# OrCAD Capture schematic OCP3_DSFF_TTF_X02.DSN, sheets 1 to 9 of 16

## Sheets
1 PAGE01 - Block Diagram: size Custom; title: OCP NIC 3.0 DSFF Thermal Test Fixture; rev: X02; company: Dell, Inc.; note: 9XNGK; note: 200 Dell Way; note: Round Rock, TX 78682
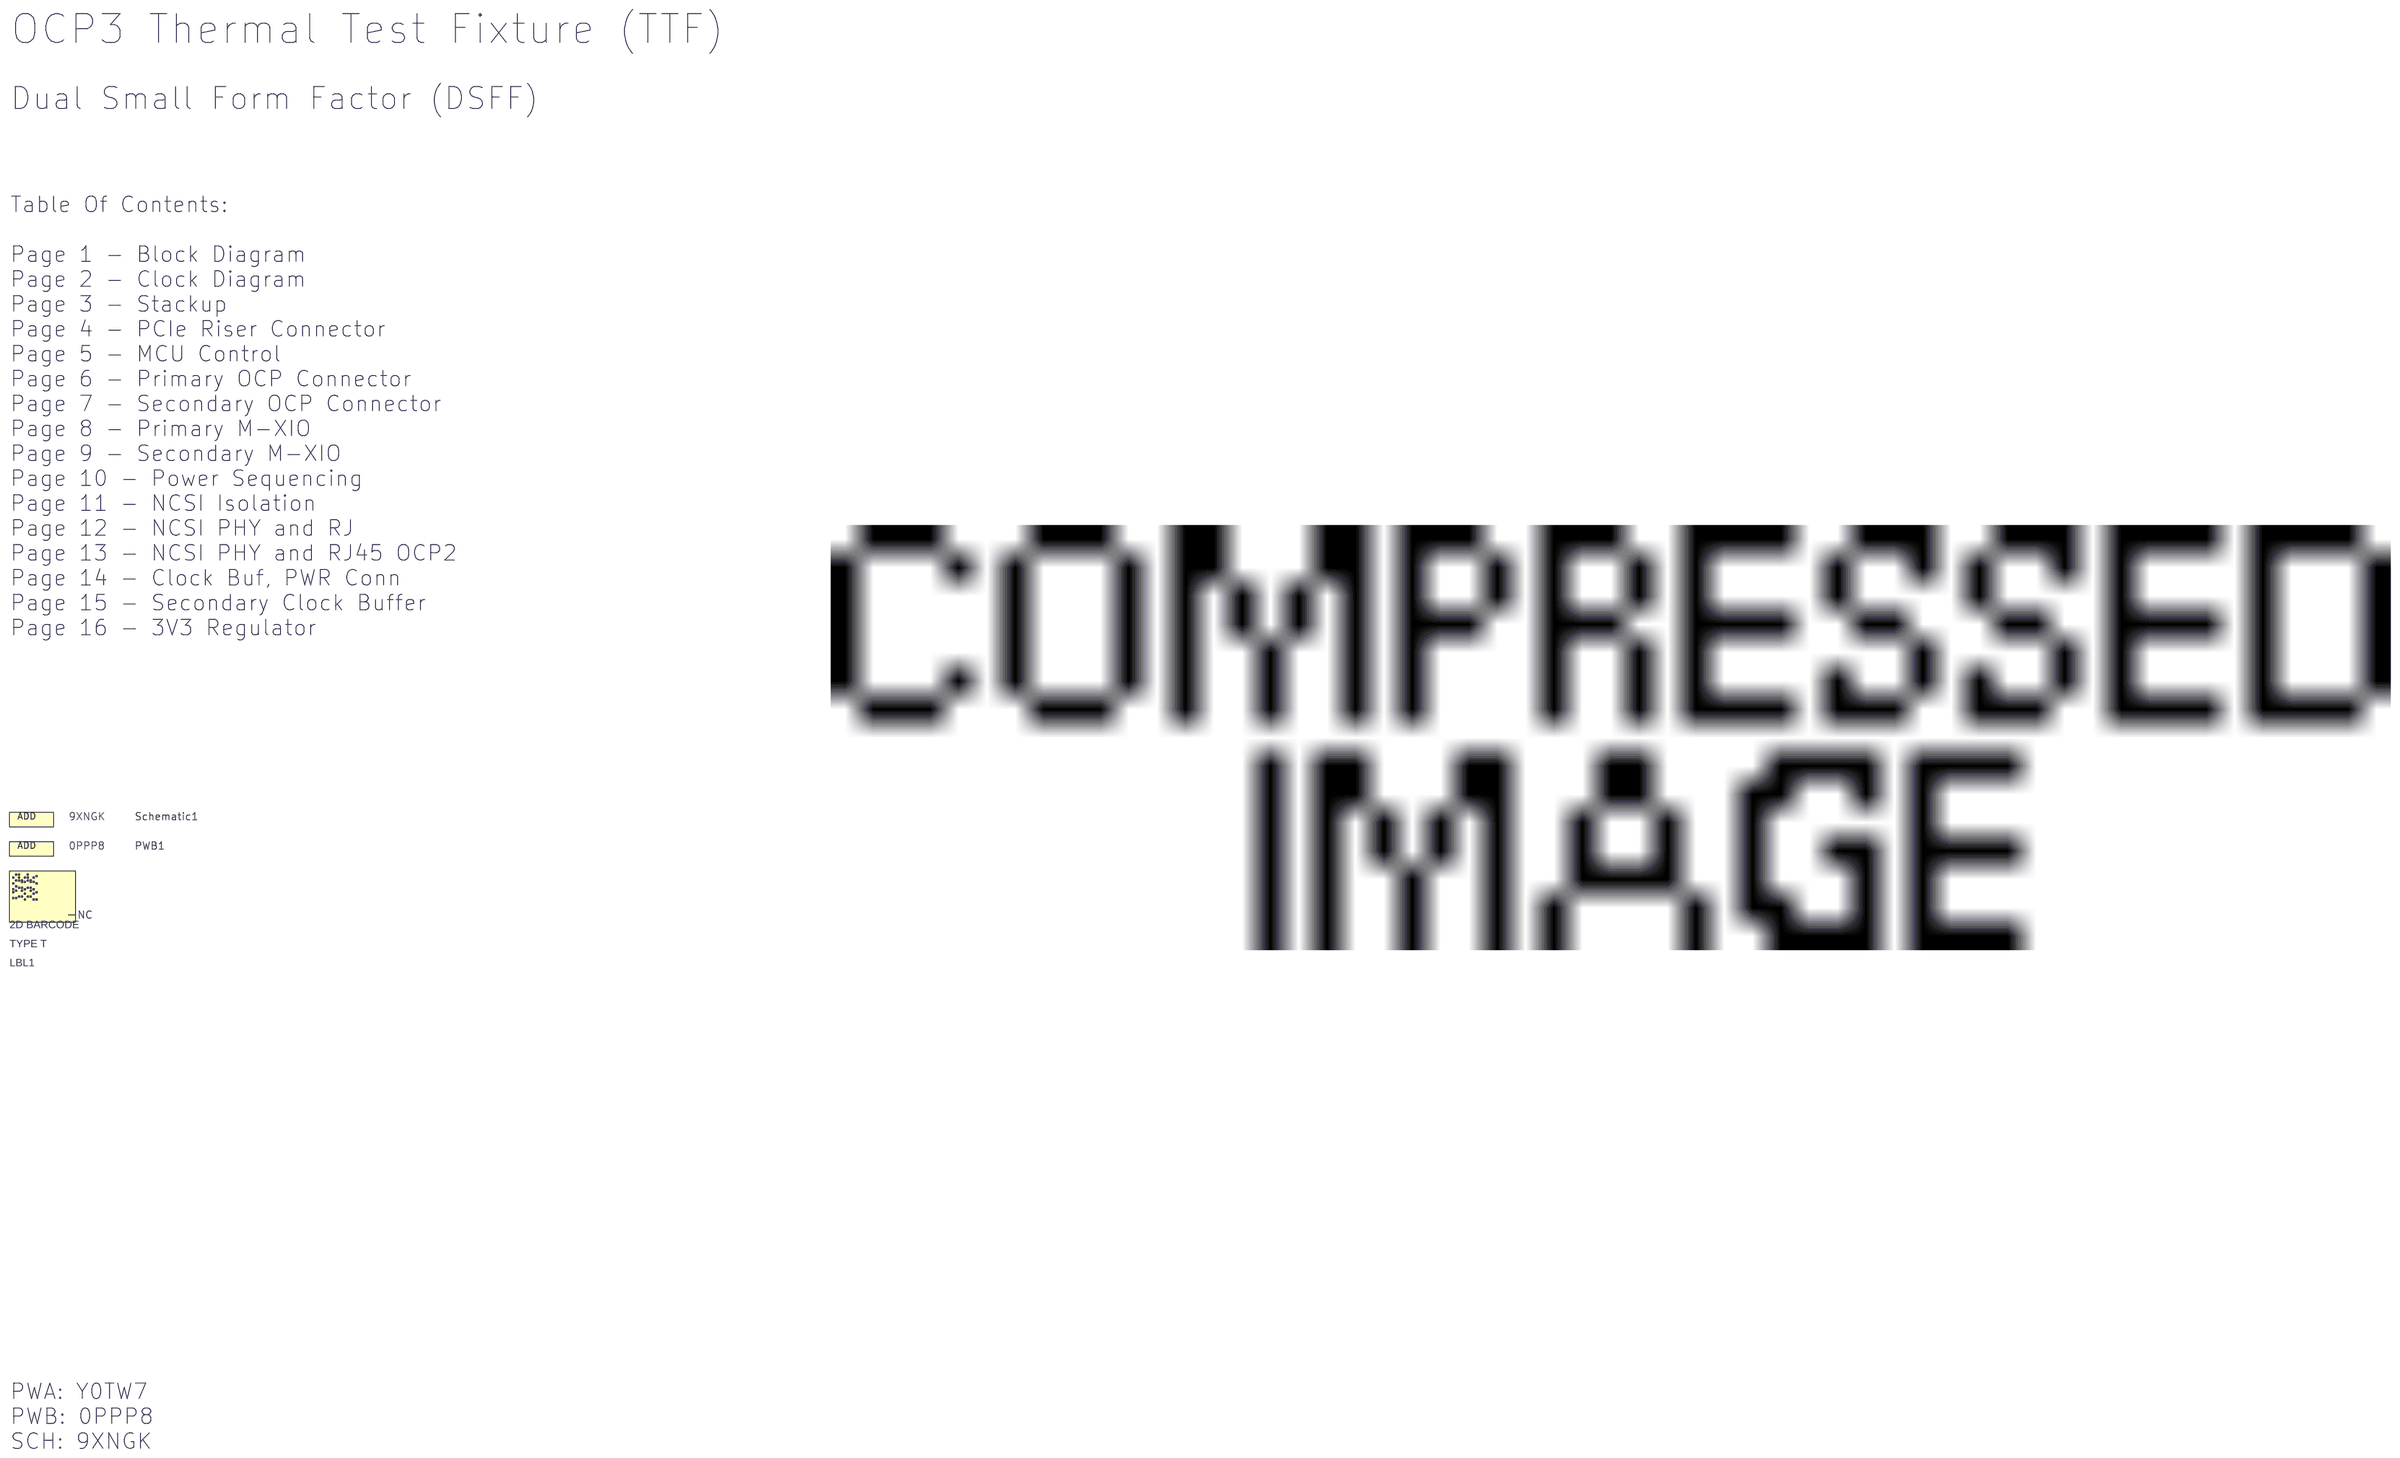
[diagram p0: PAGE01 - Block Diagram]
2 PAGE02 - Clock Diagram
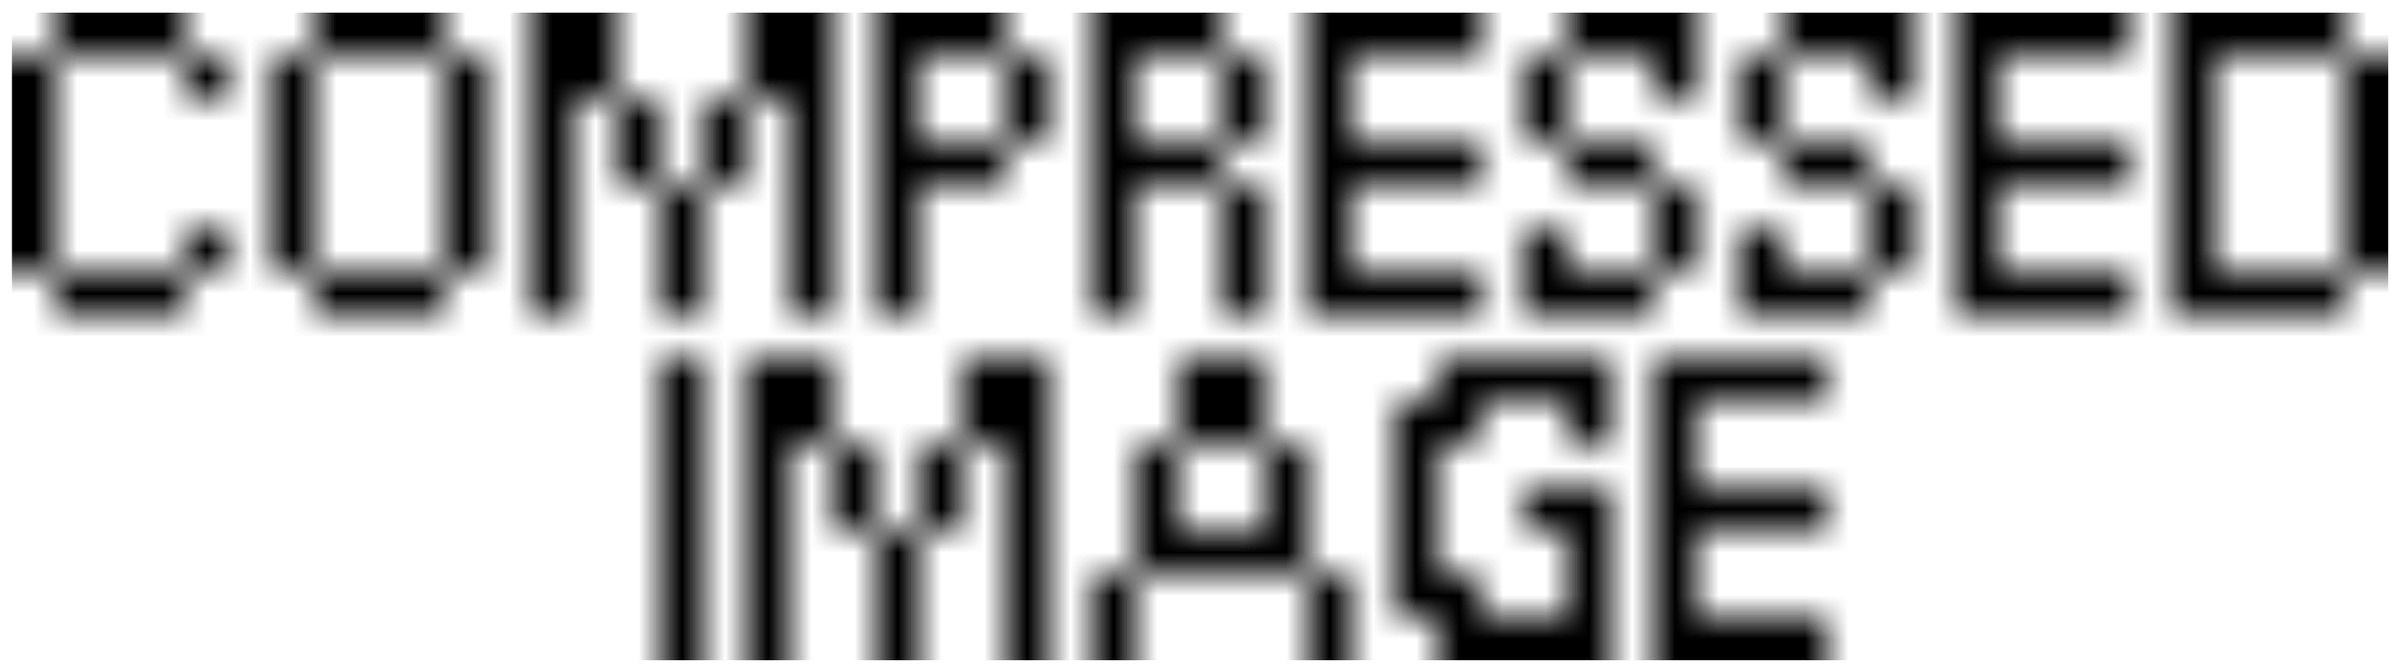
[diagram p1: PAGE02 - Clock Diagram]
3 PAGE03 - Stackup
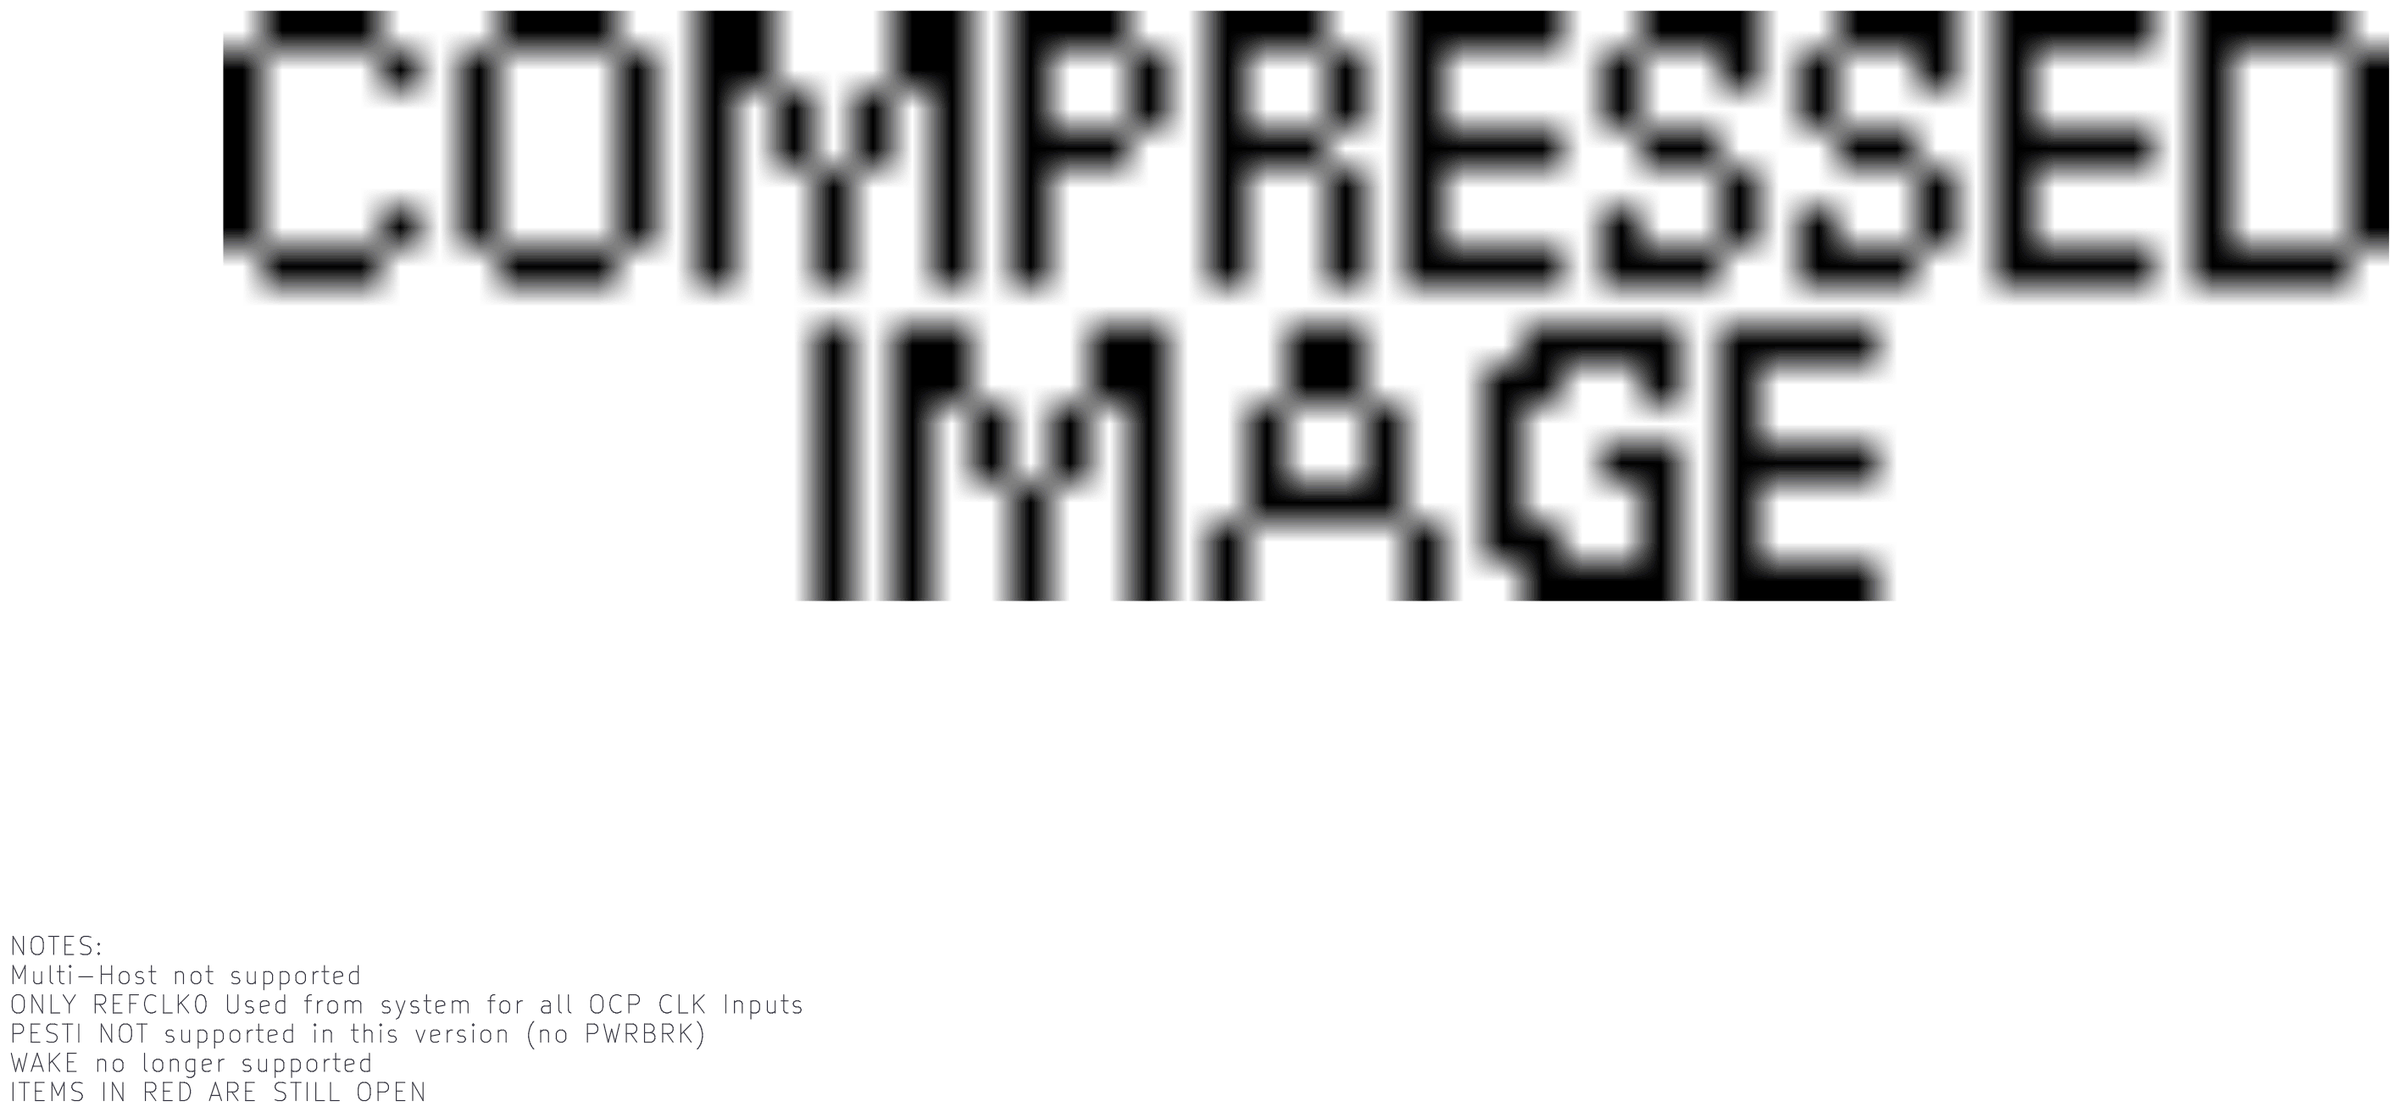
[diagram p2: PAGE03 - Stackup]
4 PAGE04 - PCIe Riser Conn: size Custom
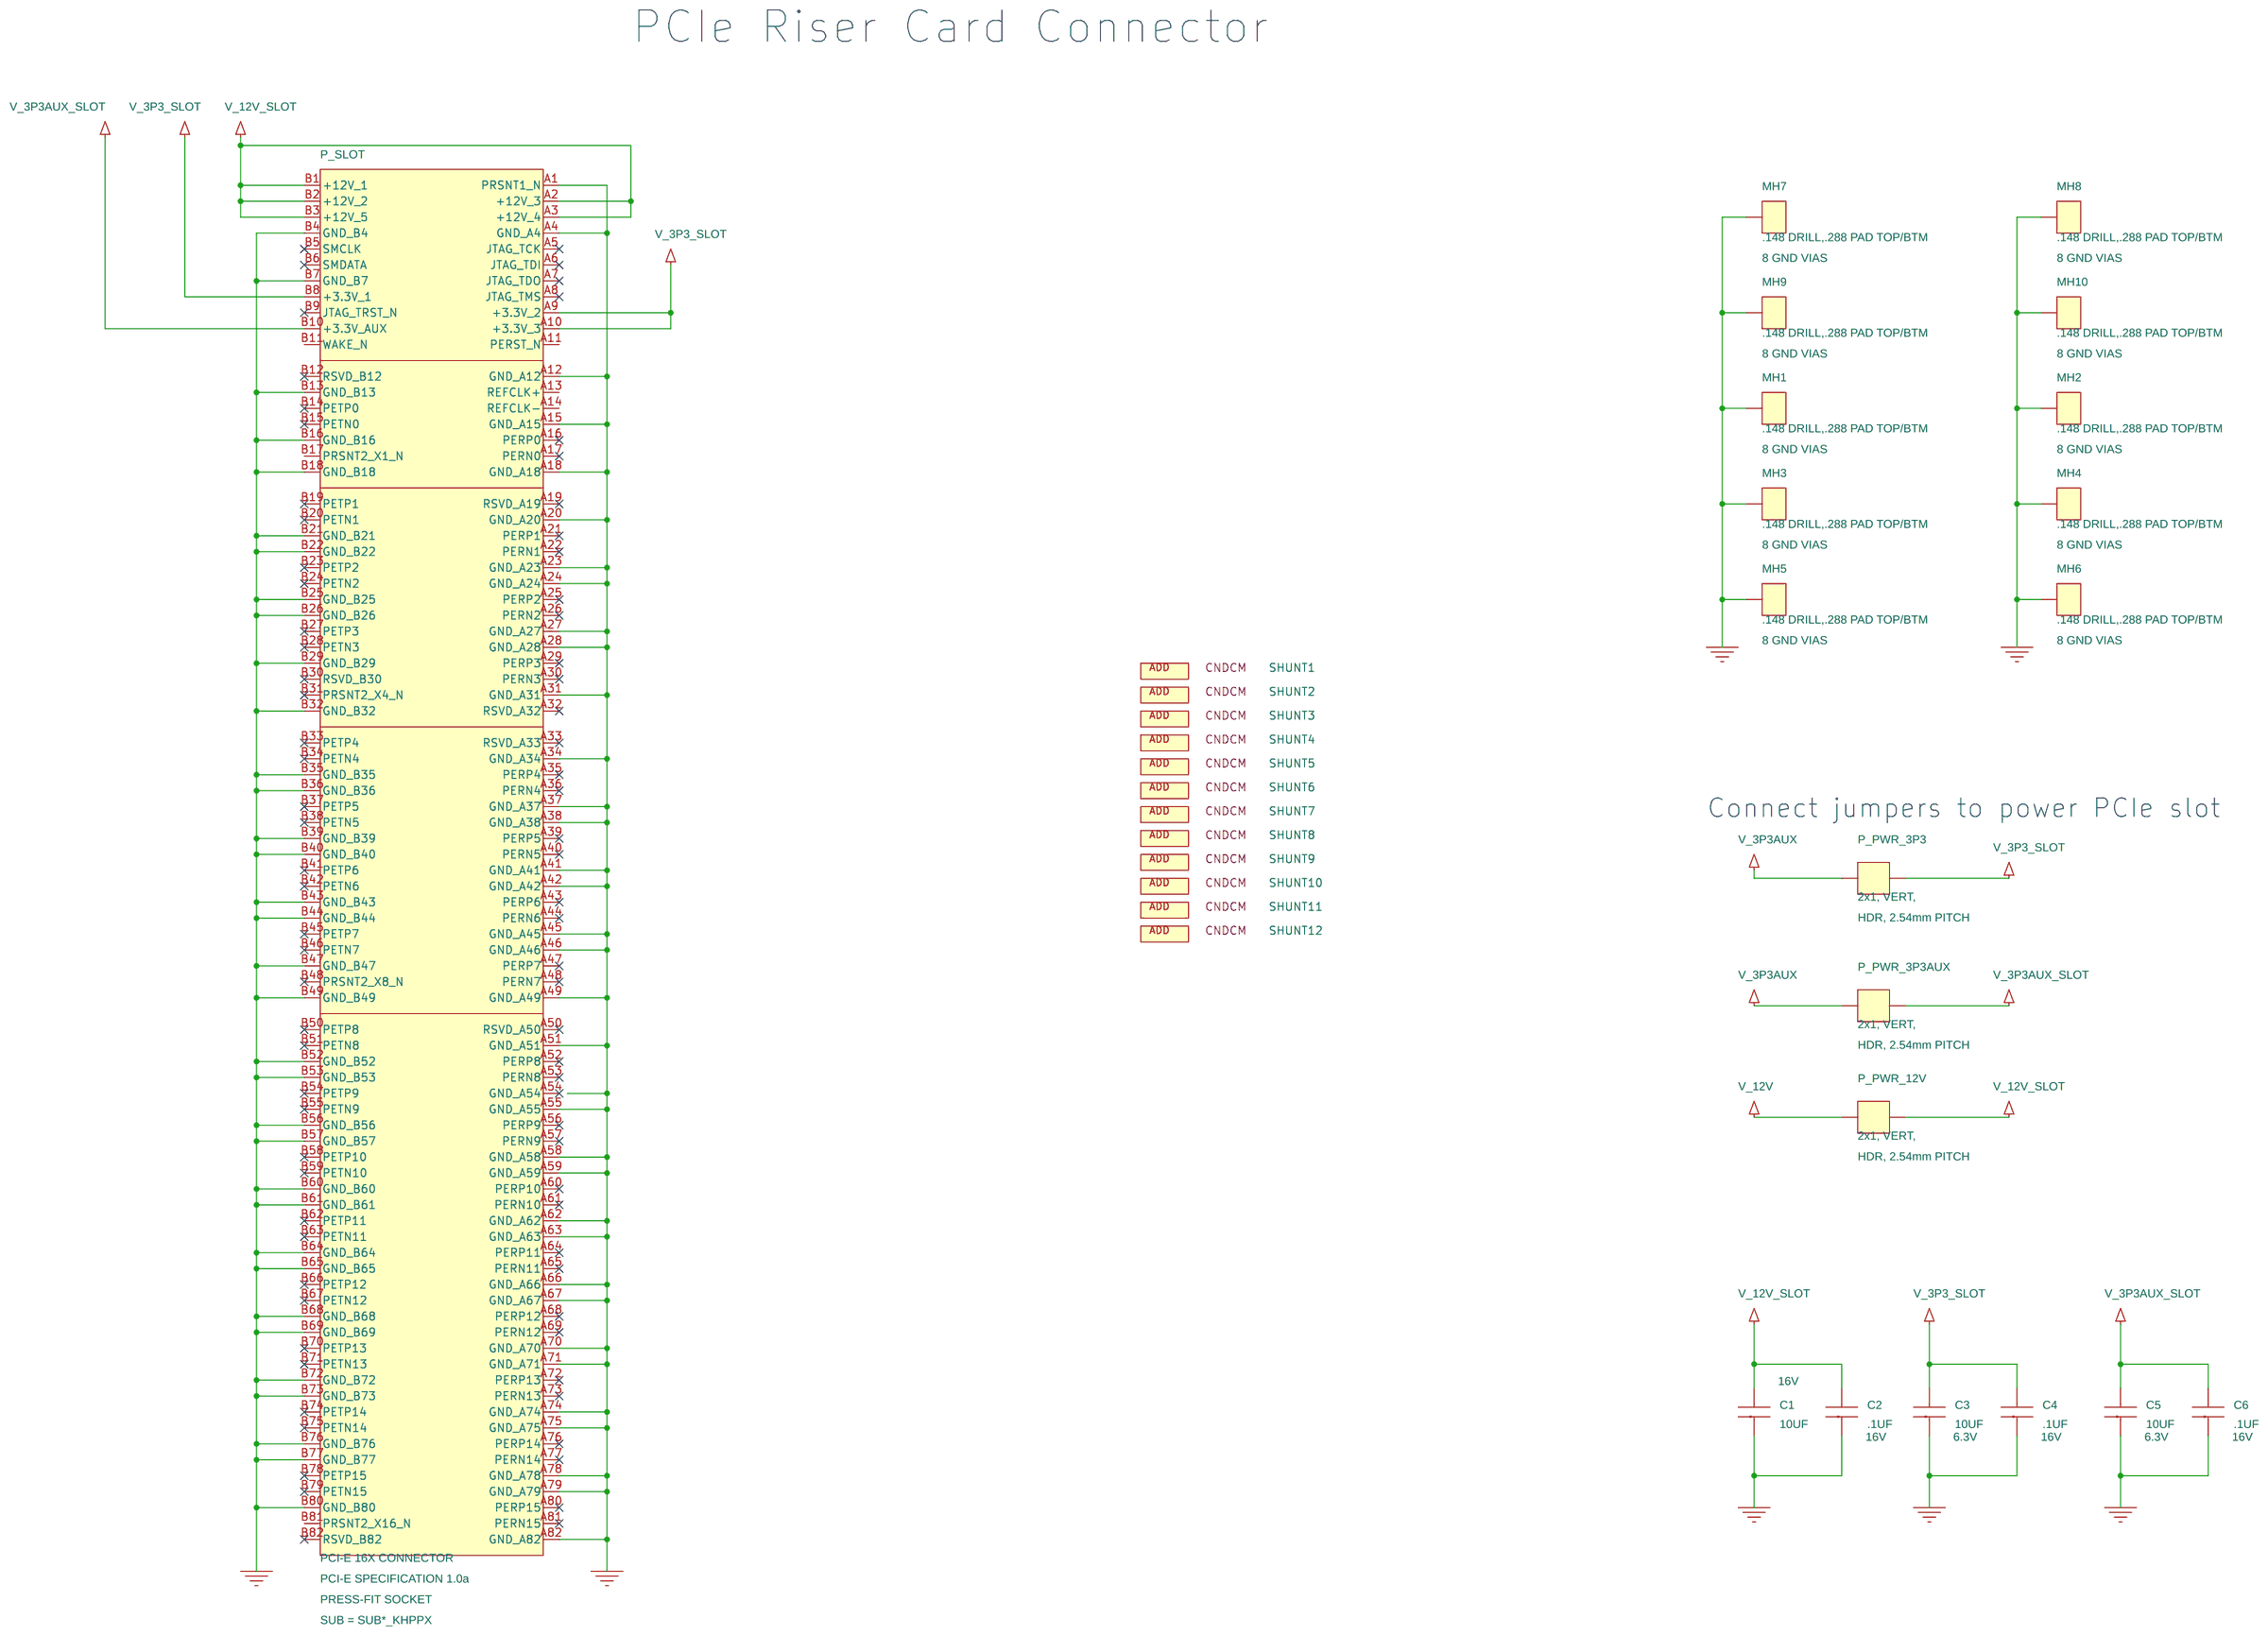
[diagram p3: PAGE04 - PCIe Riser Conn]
5 PAGE05 - MCU Control: size Custom
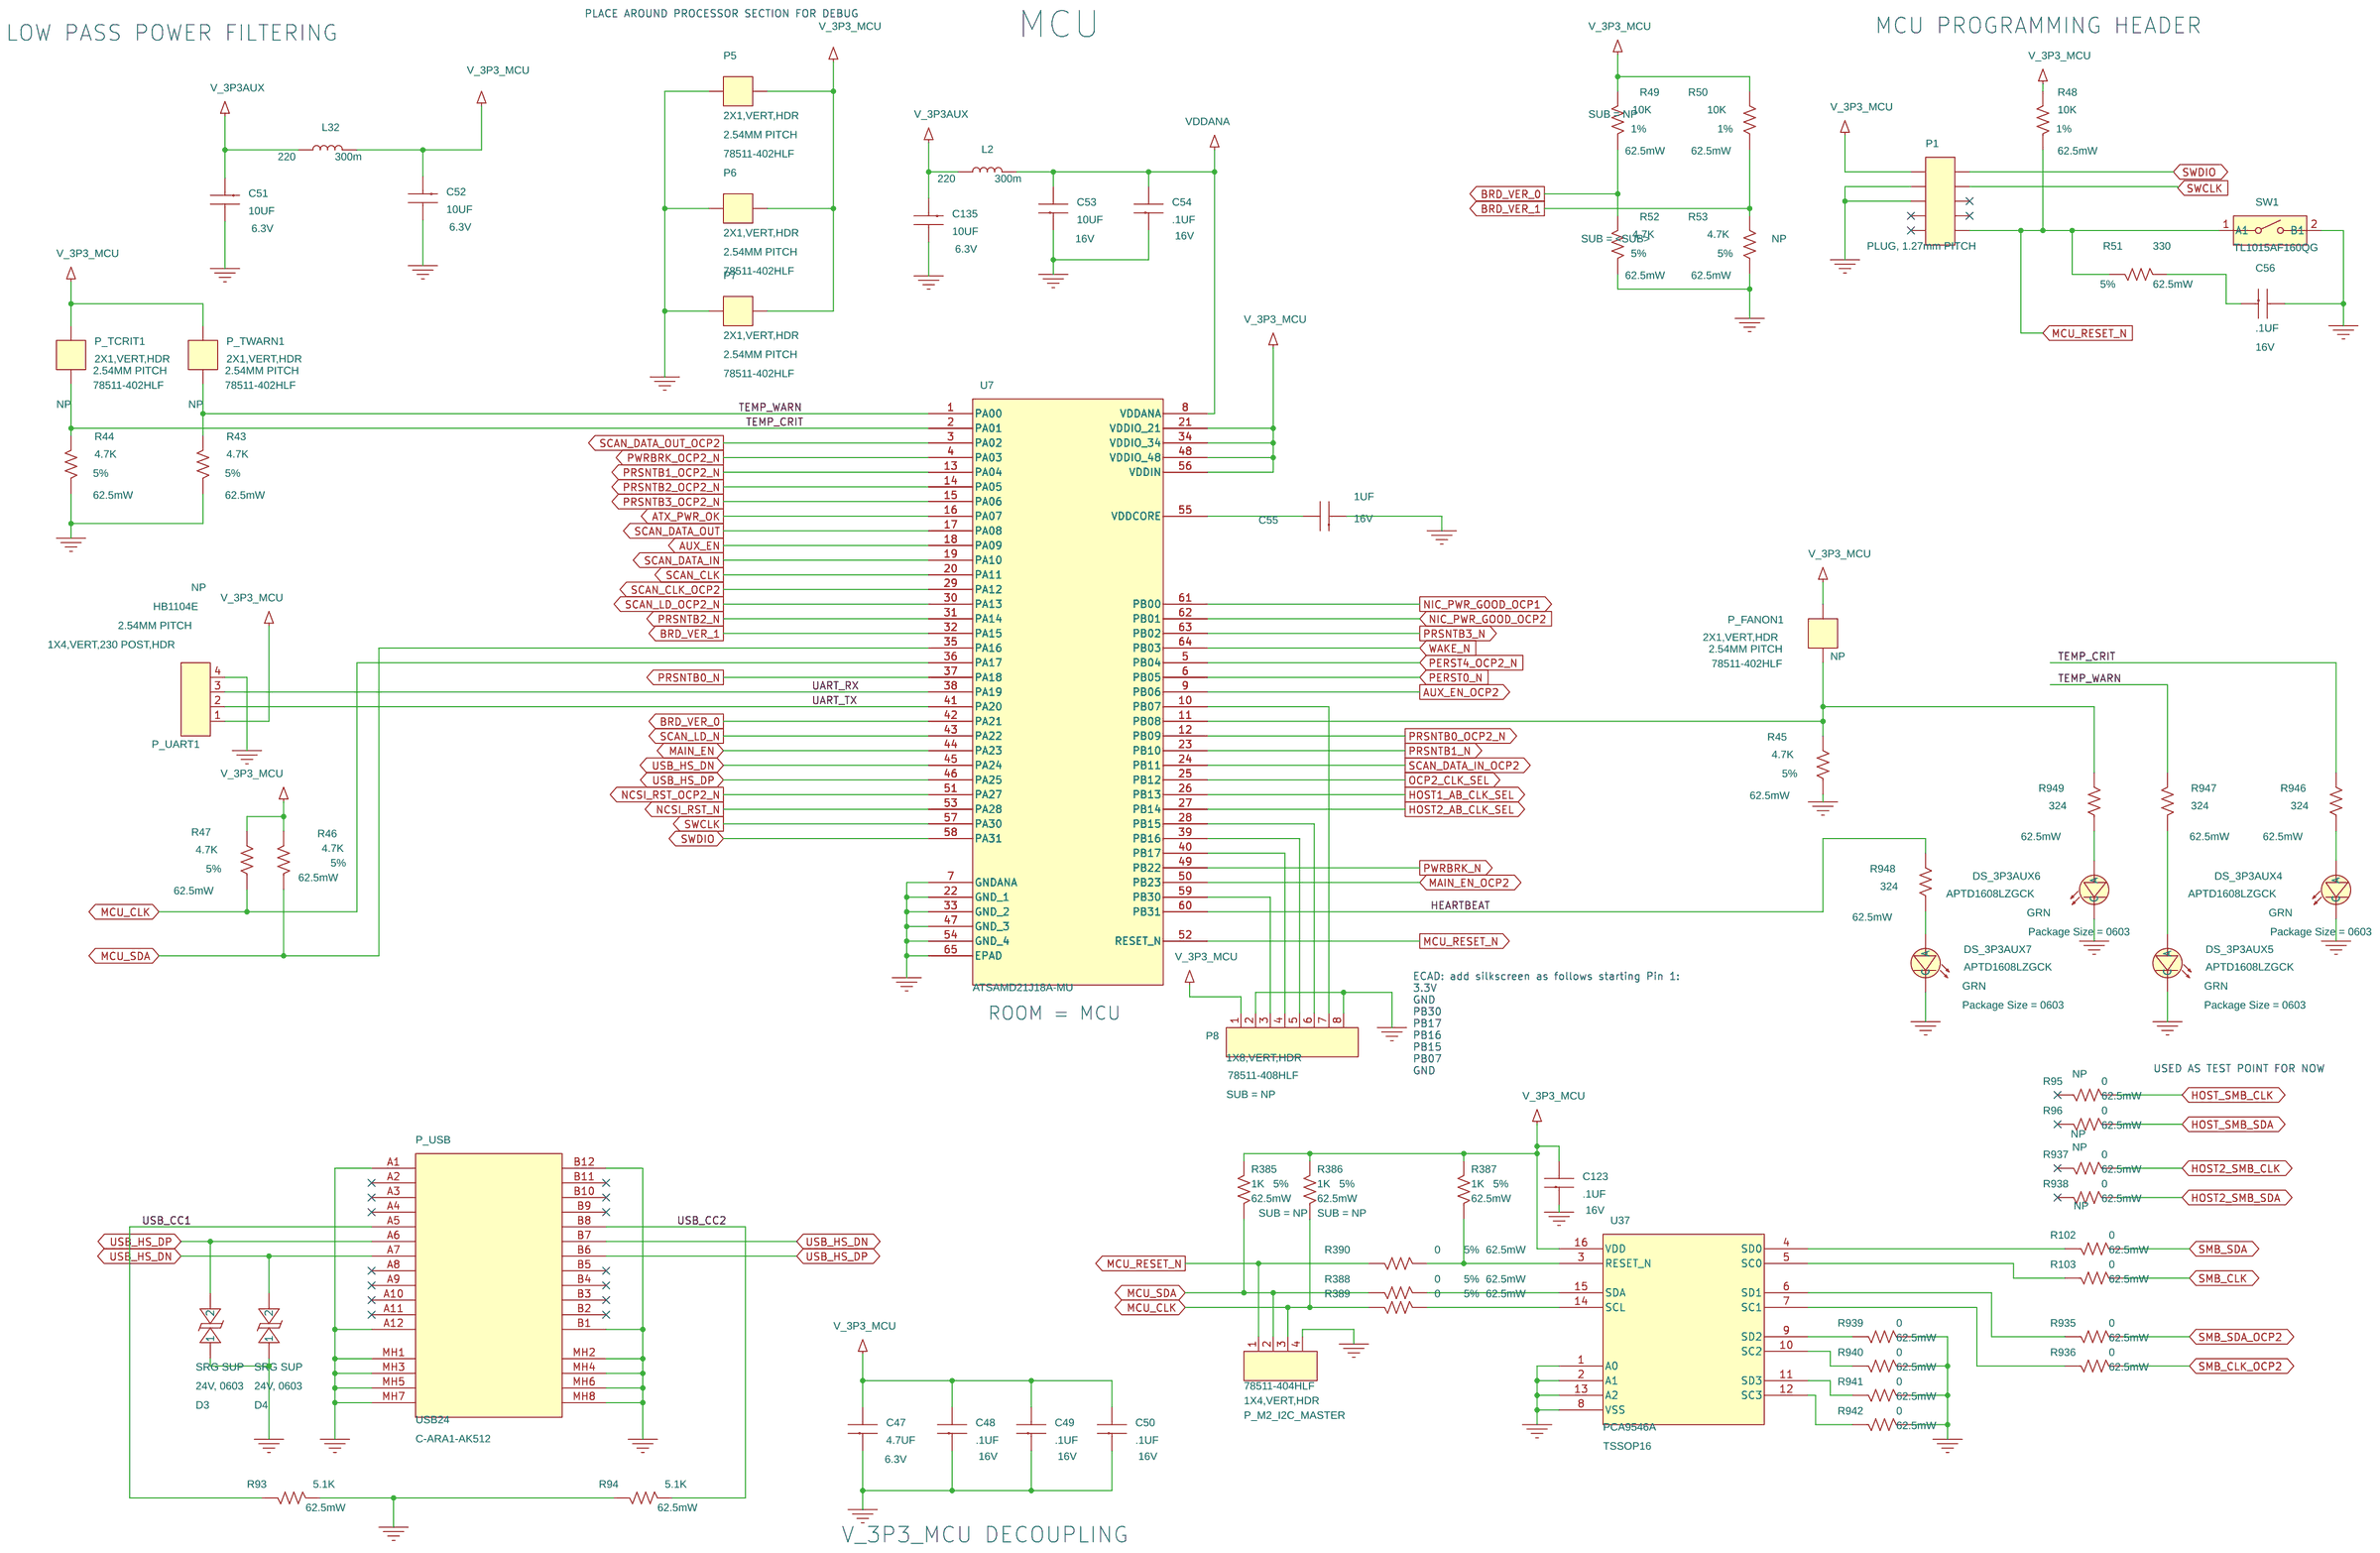
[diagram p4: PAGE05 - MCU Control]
6 PAGE06 - Primary OCP Conn: size Custom
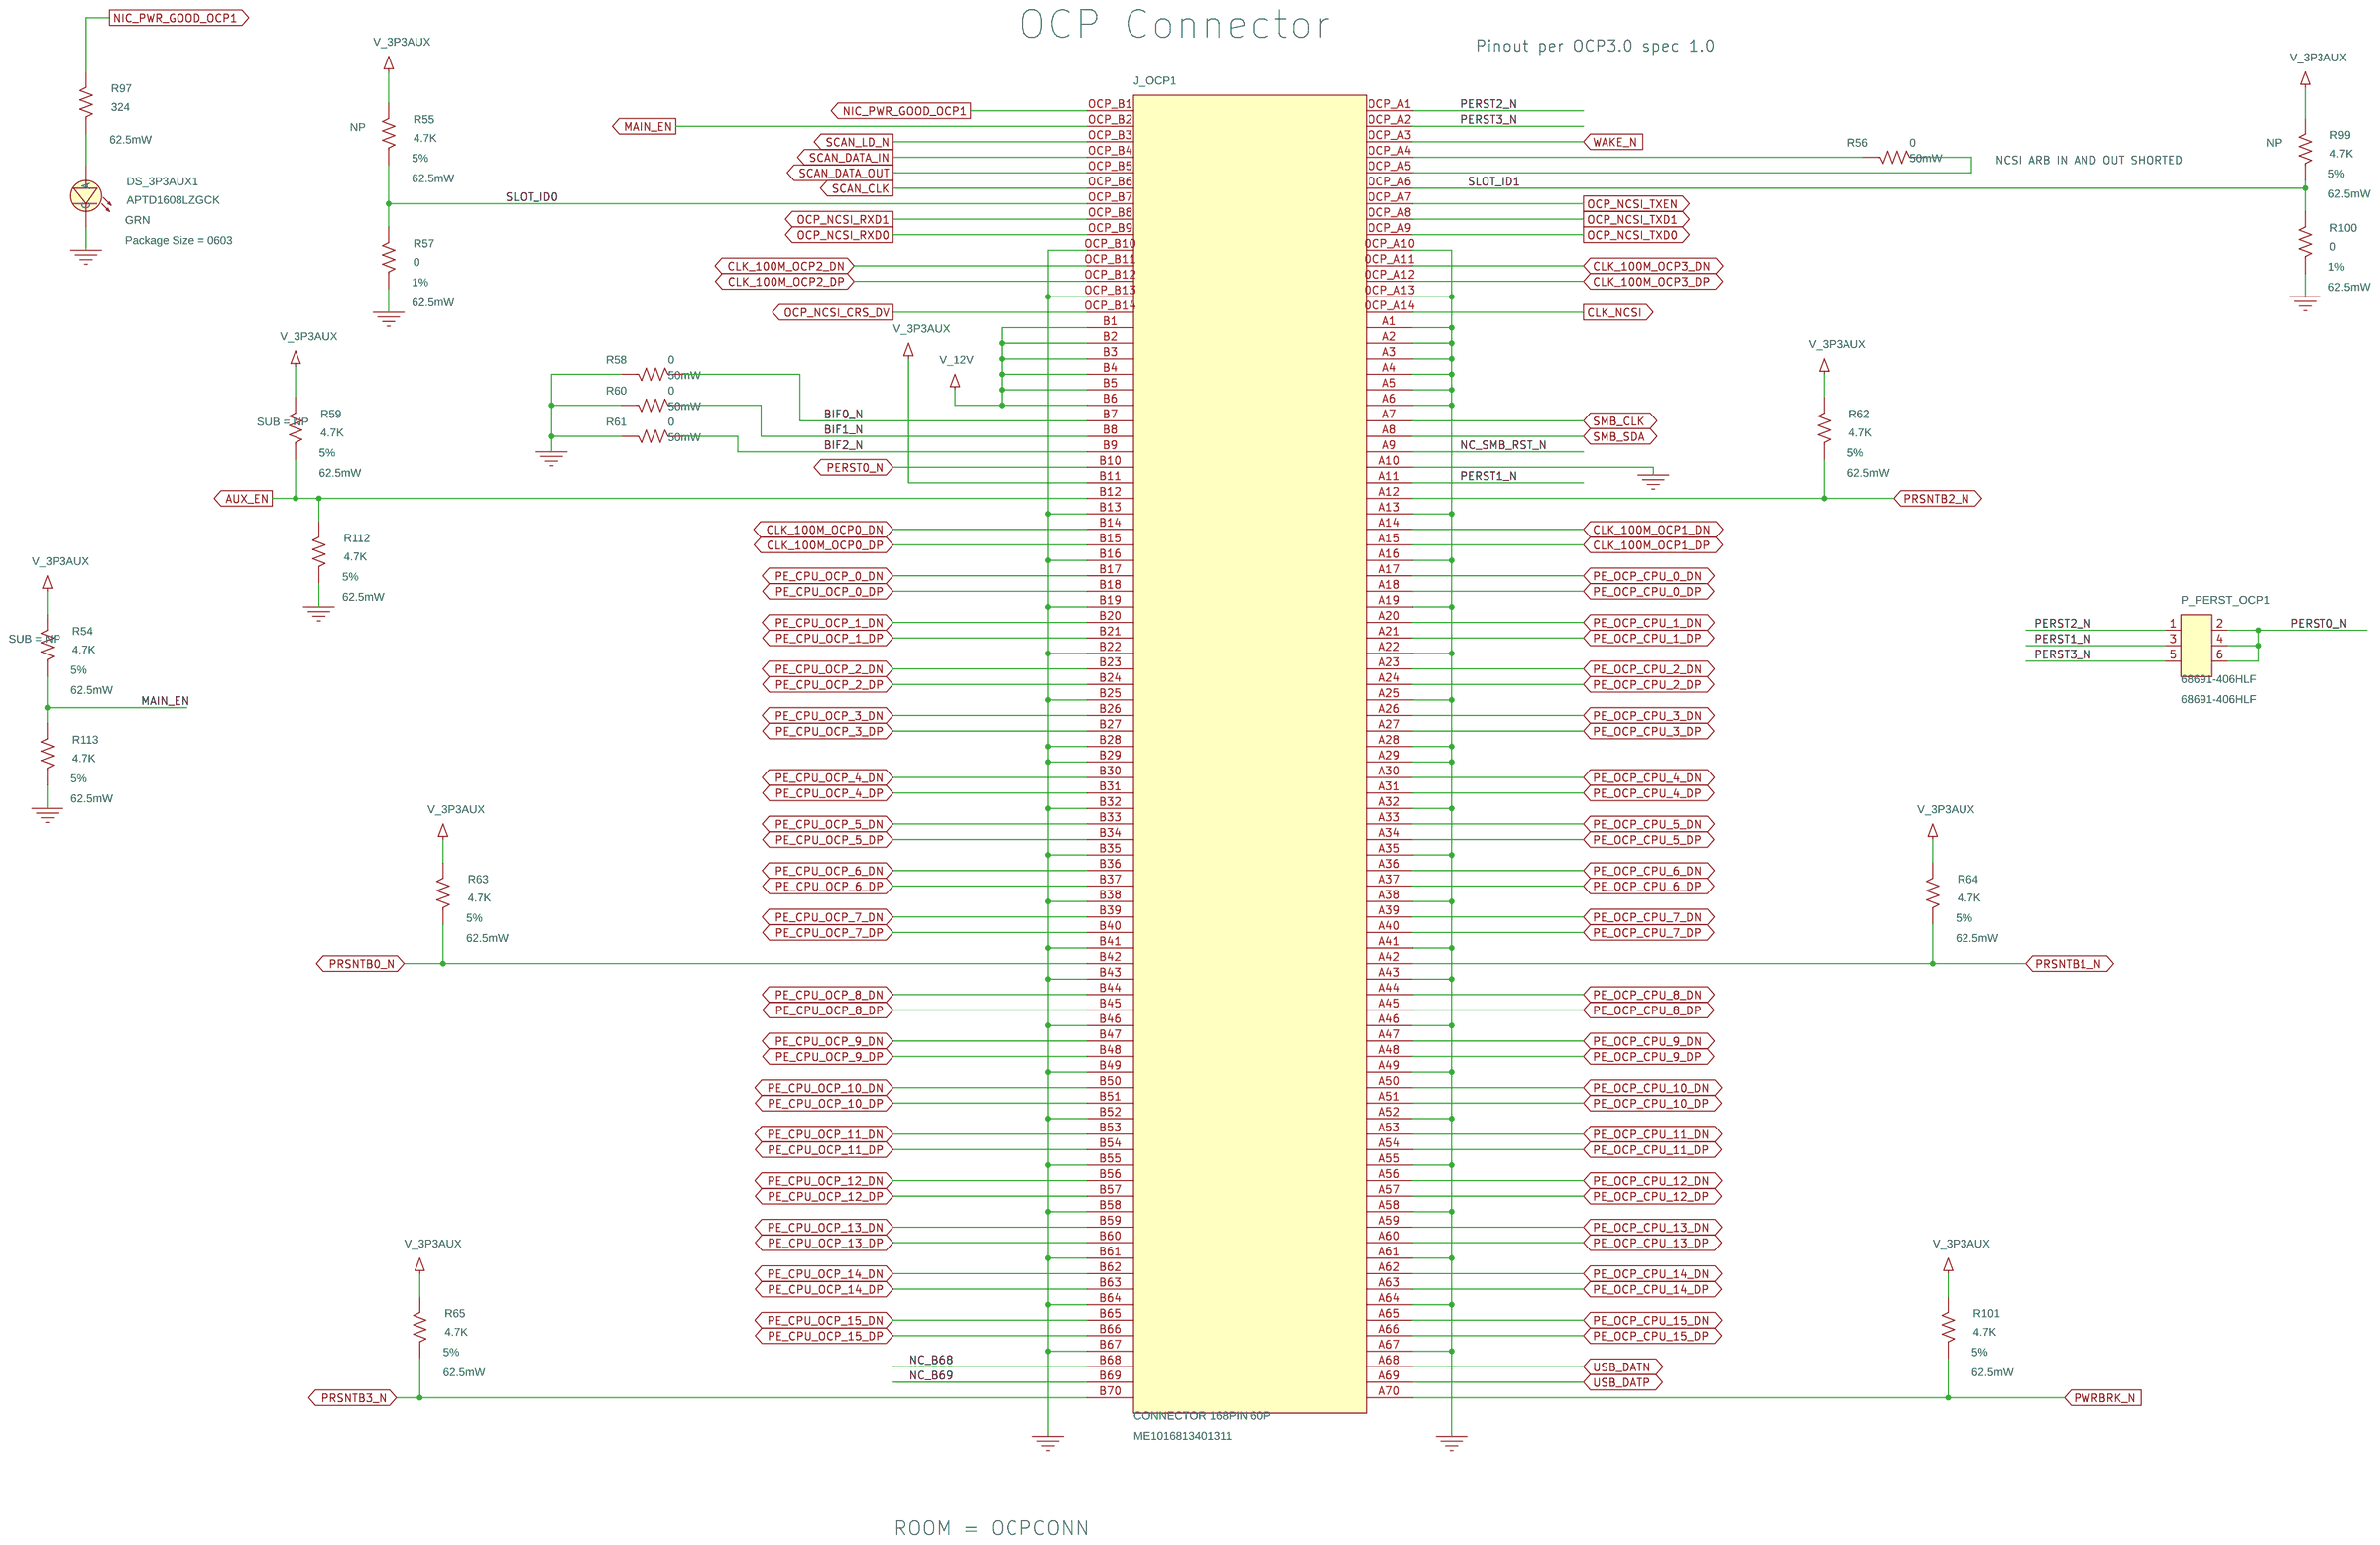
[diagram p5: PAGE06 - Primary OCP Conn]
7 PAGE07 - Secondary OCP Conn: size Custom
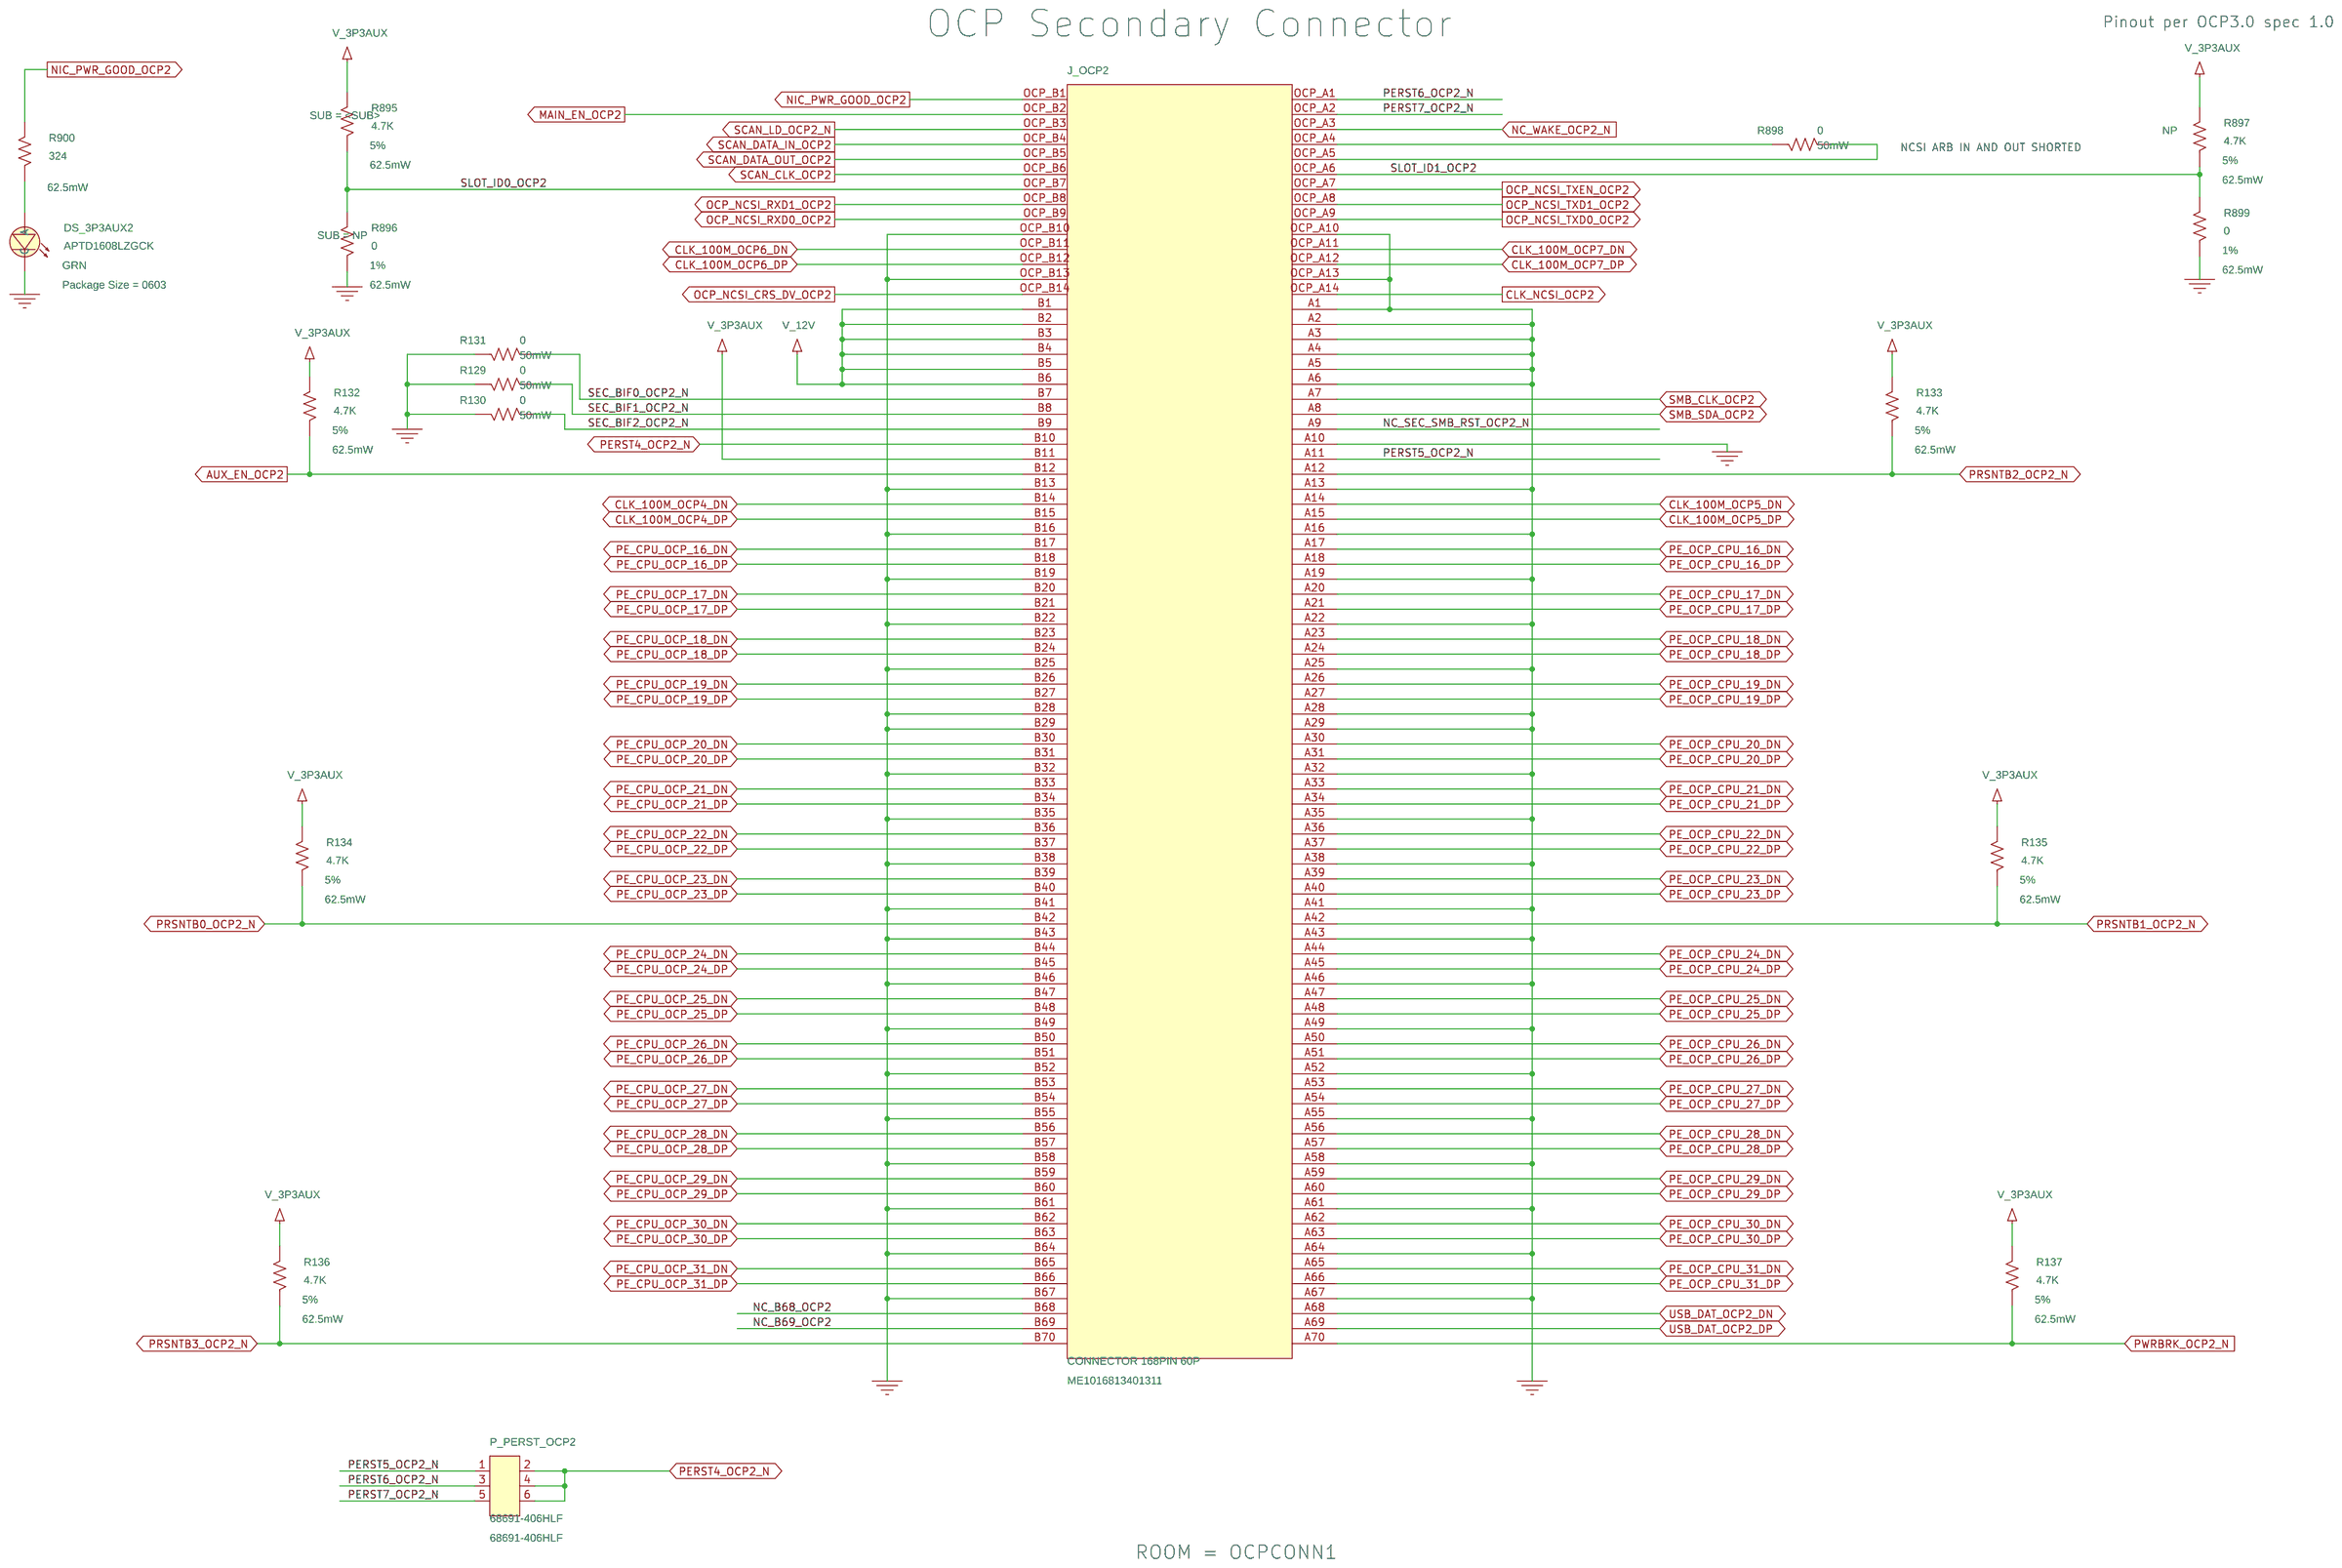
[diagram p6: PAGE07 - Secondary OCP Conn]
8 PAGE08 - Primary M-XIO + PICPWR: size Custom
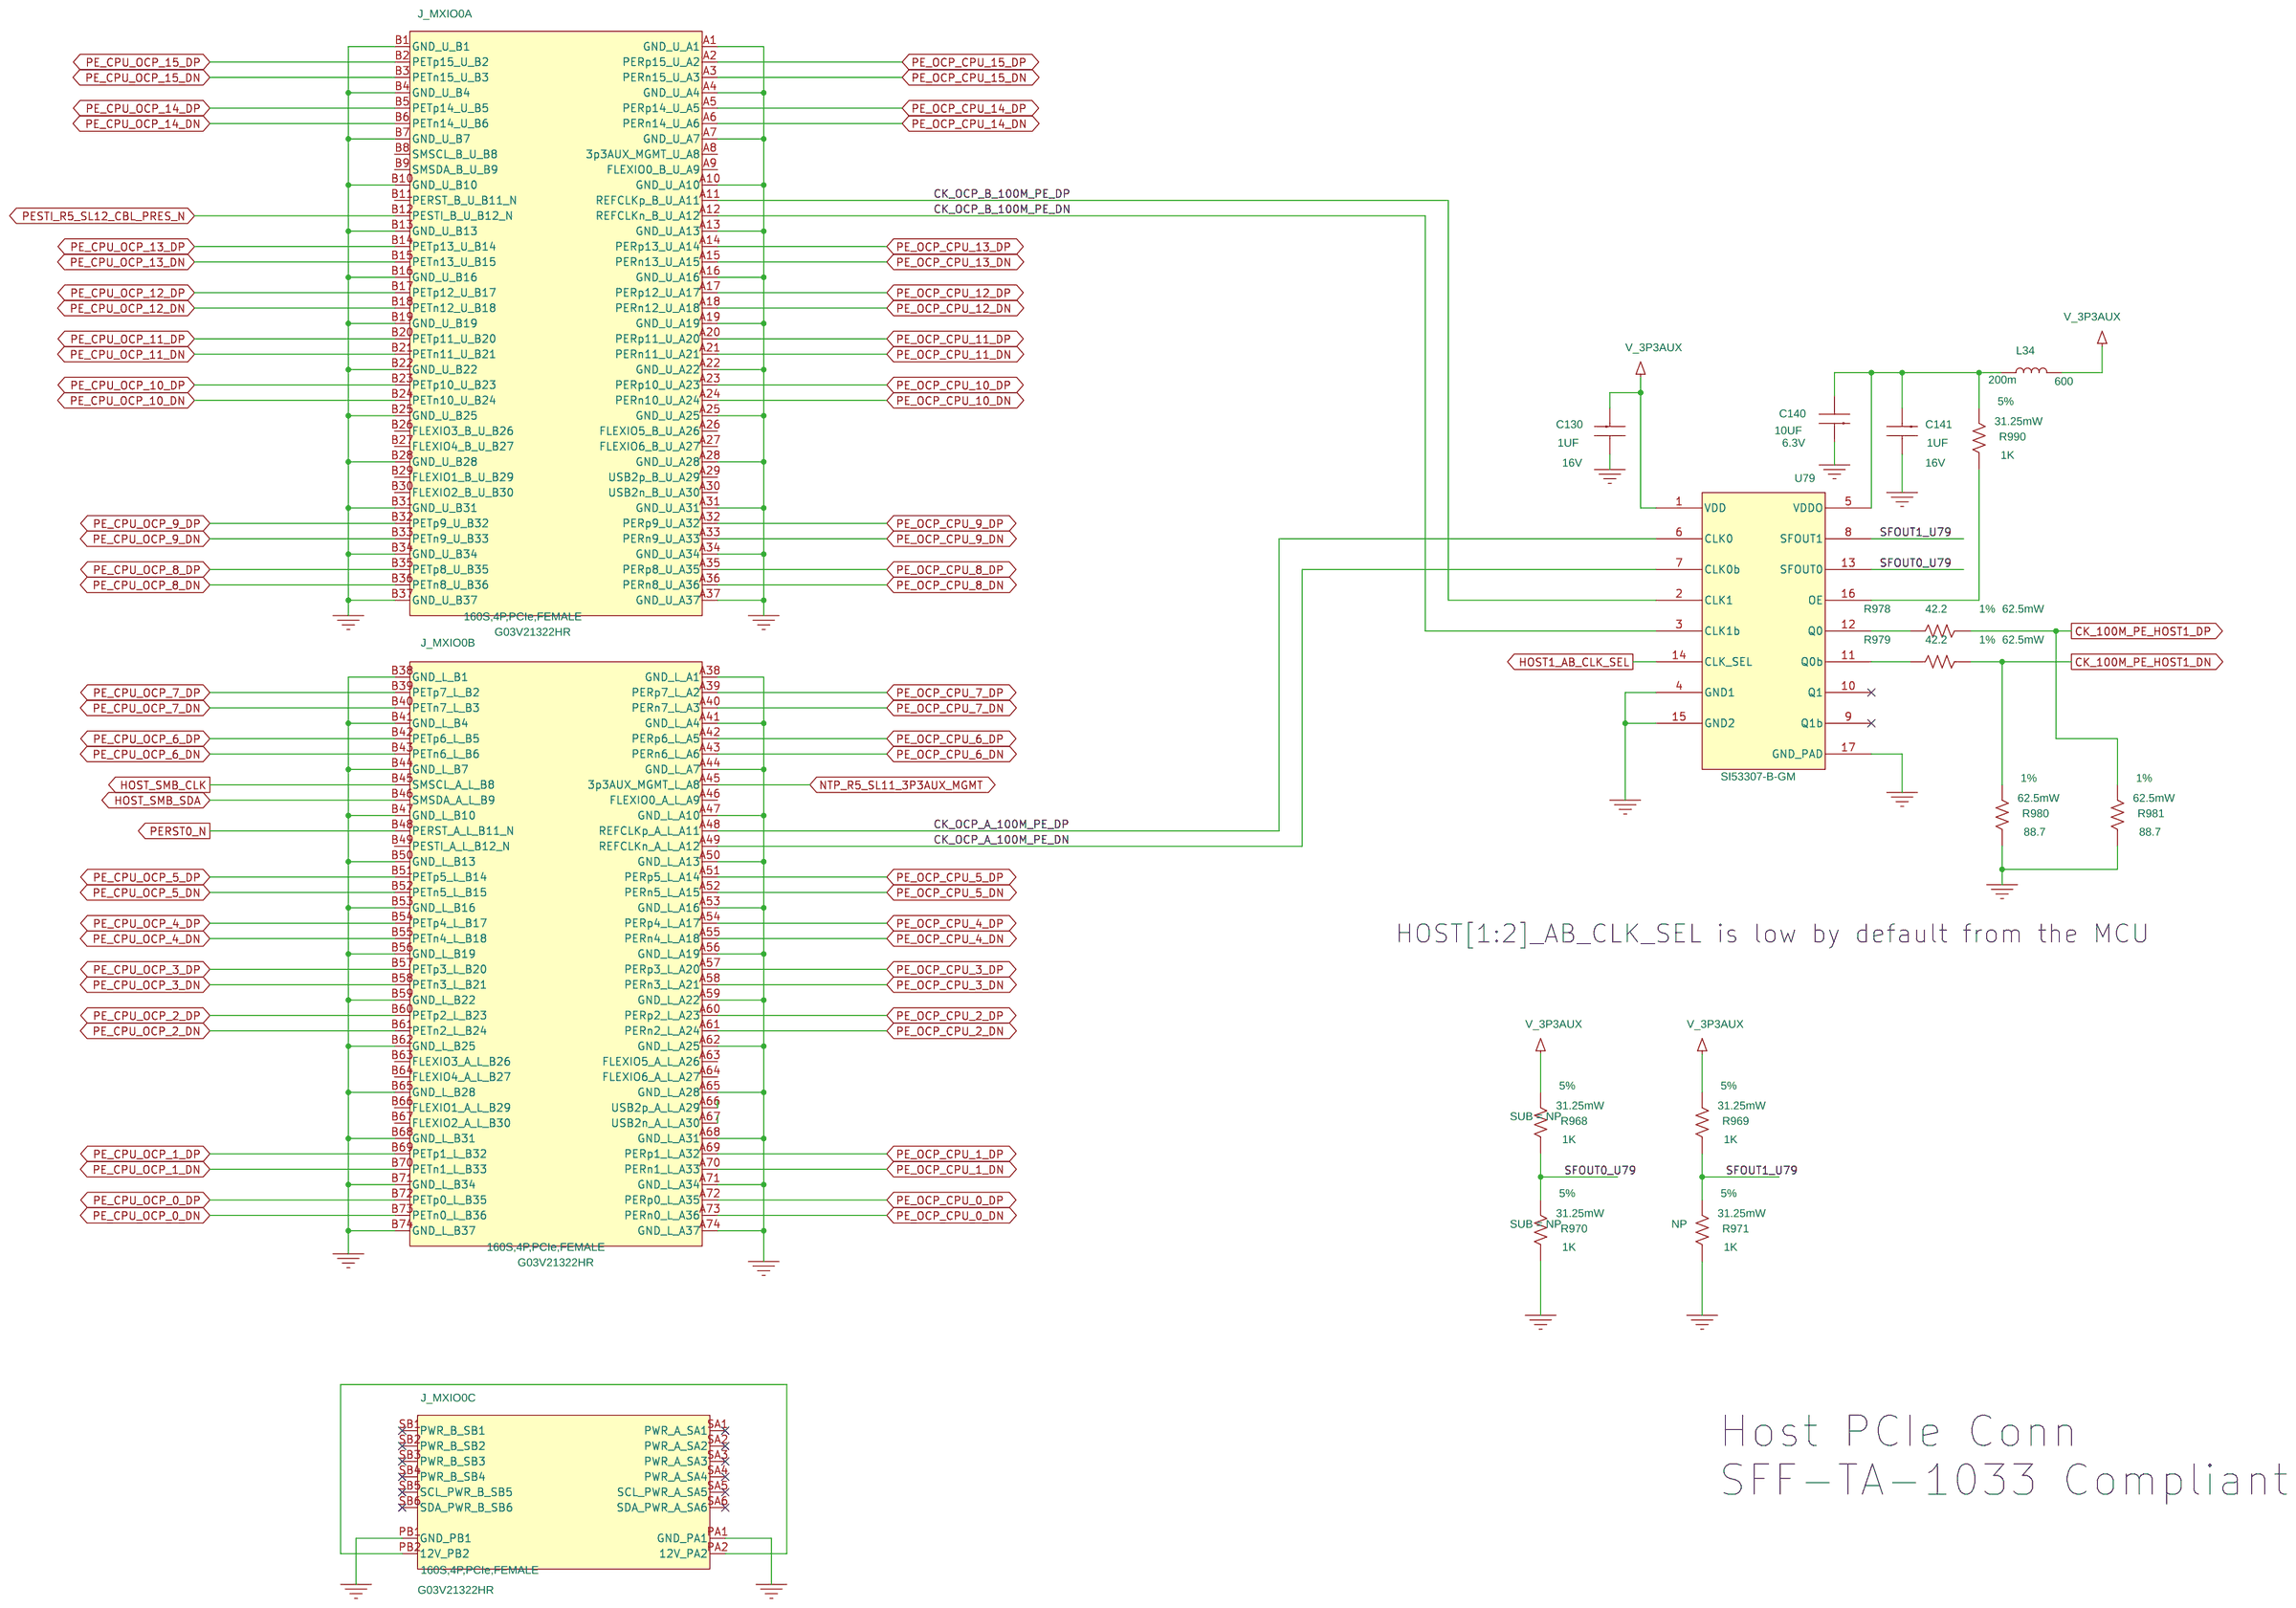
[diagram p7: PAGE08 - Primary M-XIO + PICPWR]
9 PAGE10 - Power Sequencing
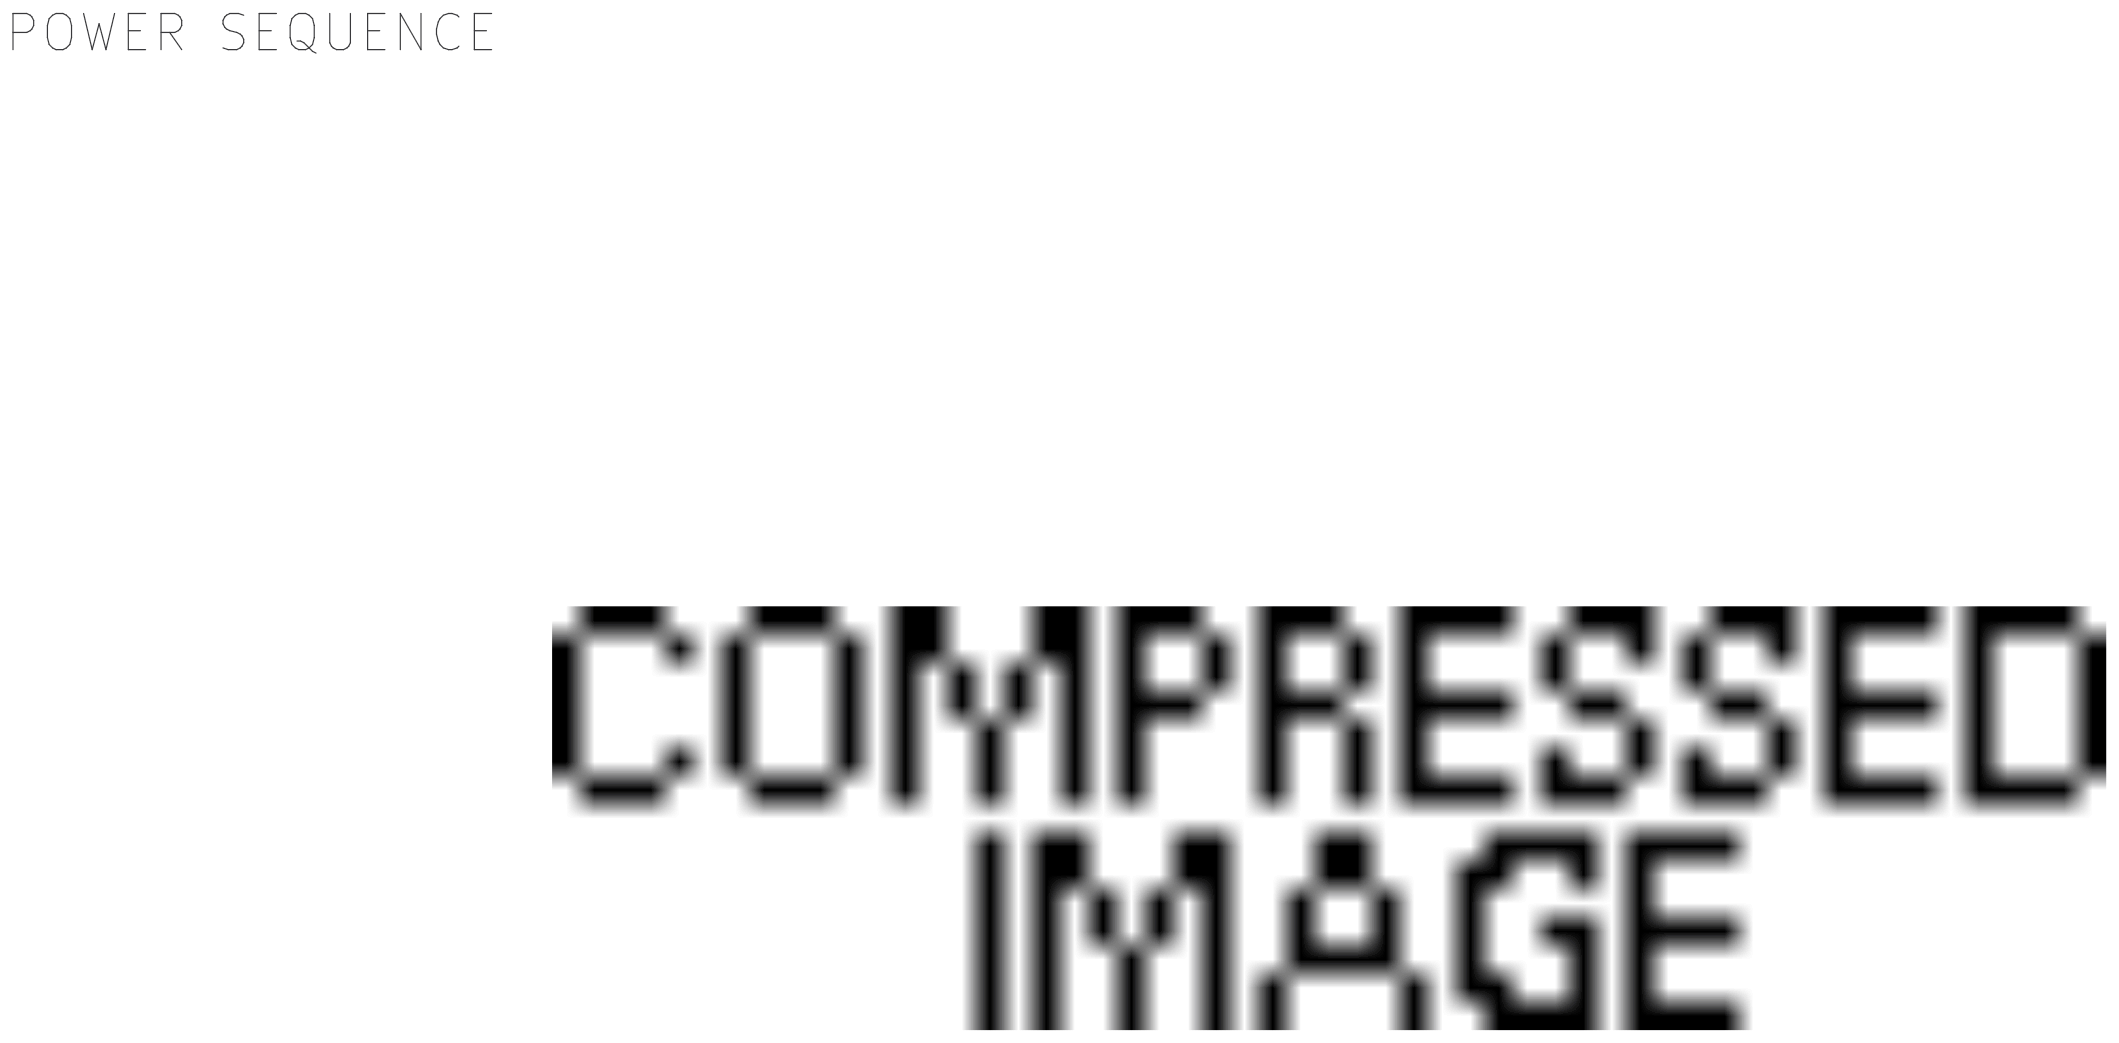
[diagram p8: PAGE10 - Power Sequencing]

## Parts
sheet PAGE01 - Block Diagram
LBL1  2d_label500x437  [2D_LABEL500X437]
PWB1  add_part
Schematic1  add_part
sheet PAGE04 - PCIe Riser Conn
C1  10UF  [C1206]
C2  .1UF  [C0402]
C3  10UF  [C0603]
C4  .1UF  [C0402]
C5  10UF  [C0603]
C6  .1UF  [C0402]
MH1  .148 DRILL,.288 PAD TOP/BTM  [MH148_G8_288TB]
MH2  .148 DRILL,.288 PAD TOP/BTM  [MH148_G8_288TB]
MH3  .148 DRILL,.288 PAD TOP/BTM  [MH148_G8_288TB]
MH4  .148 DRILL,.288 PAD TOP/BTM  [MH148_G8_288TB]
MH5  .148 DRILL,.288 PAD TOP/BTM  [MH148_G8_288TB]
MH6  .148 DRILL,.288 PAD TOP/BTM  [MH148_G8_288TB]
MH7  .148 DRILL,.288 PAD TOP/BTM  [MH148_G8_288TB]
MH8  .148 DRILL,.288 PAD TOP/BTM  [MH148_G8_288TB]
MH9  .148 DRILL,.288 PAD TOP/BTM  [MH148_G8_288TB]
MH10  .148 DRILL,.288 PAD TOP/BTM  [MH148_G8_288TB]
P_PWR_3P3  g_2x1  [BERG1X2]
P_PWR_3P3AUX  g_2x1  [BERG1X2]
P_PWR_12V  g_2x1  [BERG1X2]
P_SLOT  c2x82_pcie_16x_skt  [C2X82_PCIE_16X_SKT_PF]
SHUNT1  add_part
SHUNT2  add_part
SHUNT3  add_part
SHUNT4  add_part
SHUNT5  add_part
SHUNT6  add_part
SHUNT7  add_part
SHUNT8  add_part
SHUNT9  add_part
SHUNT10  add_part
SHUNT11  add_part
SHUNT12  add_part
sheet PAGE05 - MCU Control
C47  4.7UF  [C0603]
C48  .1UF  [C0402]
C49  .1UF  [C0402]
C50  .1UF  [C0402]
C51  10UF  [C0805]
C52  10UF  [C0805]
C53  10UF  [C0603]
C54  .1UF  [C0402]
C55  1UF  [C0603]
C56  .1UF  [C0402]
C123  .1UF  [C0402]
C135  10UF  [C0805]
D3  g_diode_bi_tvs  [FUSE_ESD_0603]
D4  g_diode_bi_tvs  [FUSE_ESD_0603]
DS_3P3AUX4  APTD1608LZGCK  [LEDC1608X95N]
DS_3P3AUX5  APTD1608LZGCK  [LEDC1608X95N]
DS_3P3AUX6  APTD1608LZGCK  [LEDC1608X95N]
DS_3P3AUX7  APTD1608LZGCK  [LEDC1608X95N]
L2  220  [FB1005X55N]
L32  220  [FB1005X55N]
P1  g_2x5_oe  [H2X5STM_1P27SM_2P92DV]
P5  2X1,VERT,HDR  [BERG1X2]
P6  2X1,VERT,HDR  [BERG1X2]
P7  2X1,VERT,HDR  [BERG1X2]
P8  1X8,VERT,HDR  [BERG1X8]
P_FANON1  2X1,VERT,HDR  [BERG1X2]
P_M2_I2C_MASTER  1X4,VERT,HDR  [BERG1X4]
P_TCRIT1  2X1,VERT,HDR  [BERG1X2]
P_TWARN1  2X1,VERT,HDR  [BERG1X2]
P_UART1  1X4,VERT,230 POST,HDR  [BERG1X4_POST230]
P_USB  USB24  [con_cnc_tech_c_ara_ak512]
R43  4.7K  [R0402]
R44  4.7K  [R0402]
R45  4.7K  [R0402]
R46  4.7K  [R0402]
R47  4.7K  [R0402]
R48  10K  [R0402]
R49  10K  [R0402]
R50  10K  [R0402]
R51  330  [R0402]
R52  4.7K  [R0402]
R53  4.7K  [R0402]
R93  5.1K  [R0402]
R94  5.1K  [R0402]
R95  0  [R0402]
R96  0  [R0402]
R102  0  [R0402]
R103  0  [R0402]
R385  1K  [R0402]
R386  1K  [R0402]
R387  1K  [R0402]
R388  0  [R0402]
R389  0  [R0402]
R390  0  [R0402]
R935  0  [R0402]
R936  0  [R0402]
R937  0  [R0402]
R938  0  [R0402]
R939  0  [R0402]
R940  0  [R0402]
R941  0  [R0402]
R942  0  [R0402]
R946  324  [R0402]
R947  324  [R0402]
R948  324  [R0402]
R949  324  [R0402]
SW1  sw_tl1015af160qg  [2PSM_4P15X3P15]
U7  ATSAMD21J18A-MU  [QFN50P900X900X100_65N4]
U37  PCA9546A  [TSOP65P640X110_16N]
sheet PAGE06 - Primary OCP Conn
DS_3P3AUX1  APTD1608LZGCK  [LEDC1608X95N]
J_OCP1  CONNECTOR 168PIN 60P  [AMP_STRDL_168PIN_60P]
P_PERST_OCP1  68691-406HLF  [BERG2X3]
R54  4.7K  [R0402]
R55  4.7K  [R0402]
R56  0  [R0201]
R57  0  [R0402]
R58  0  [R0201]
R59  4.7K  [R0402]
R60  0  [R0201]
R61  0  [R0201]
R62  4.7K  [R0402]
R63  4.7K  [R0402]
R64  4.7K  [R0402]
R65  4.7K  [R0402]
R97  324  [R0402]
R99  4.7K  [R0402]
R100  0  [R0402]
R101  4.7K  [R0402]
R112  4.7K  [R0402]
R113  4.7K  [R0402]
sheet PAGE07 - Secondary OCP Conn
DS_3P3AUX2  APTD1608LZGCK  [LEDC1608X95N]
J_OCP2  CONNECTOR 168PIN 60P  [AMP_STRDL_168PIN_60P]
P_PERST_OCP2  68691-406HLF  [BERG2X3]
R129  0  [R0201]
R130  0  [R0201]
R131  0  [R0201]
R132  4.7K  [R0402]
R133  4.7K  [R0402]
R134  4.7K  [R0402]
R135  4.7K  [R0402]
R136  4.7K  [R0402]
R137  4.7K  [R0402]
R895  4.7K  [R0402]
R896  0  [R0402]
R897  4.7K  [R0402]
R898  0  [R0201]
R899  0  [R0402]
R900  324  [R0402]
sheet PAGE08 - Primary M-XIO + PICPWR
C130  1UF  [C0603]
C140  10UF  [C0603]
C141  1UF  [C0603]
J_MXIO0  160S,4P,PCIe,FEMALE  [AMPHENOL_G03V21322HR]  (sections A,B,C)
L34  600  [FR0603]
R968  1K  [R0402]
R969  1K  [R0402]
R970  1K  [R0402]
R971  1K  [R0402]
R978  42.2  [R0402]
R979  42.2  [R0402]
R980  88.7  [R0402]
R981  88.7  [R0402]
R990  1K  [R0402]
U79  SI53307-B-GM  [QFN50P300X300X90-17]

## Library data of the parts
LBL1 = 2d_label500x437: LABEL,2D BARCODE,.500X.437,TYPE T; DEVICE: 090730100102; Part Number: HP126; TAG1: 2D BARCODE; TAG2: TYPE T
PWB1 = add_part: Part Number: 0PPP8
Schematic1 = add_part: Part Number: 9XNGK
C1 = cap: CAP,10UF,10%,16V,X7R,1206; DEVICE: 090729120355; Part Number: TK479; ROOM: PCIE1; TOLERANCE: 10%; VOLTAGE: 16V
C2 C4 C6 = cap: CAP,.1UF,10%,16V,X7R,0402; DEVICE: 090729120334; Part Number: P8155; ROOM: PCIE1; TOLERANCE: 10%; VOLTAGE: 16V
C3 C5 = cap: CAP,10UF,20%,6.3V,X5R,0603; DEVICE: 090729120437; Part Number: YT654; ROOM: PCIE1; TOLERANCE: 20%; VOLTAGE: 6.3V
MH1-MH10 = g_1x1_mh: MT_HOLE_UNPLATED148_288PADS TOP AND BOTTOM_8GND VIAS; BOM_IGNORE: TRUE; CLASS: DISCRETE; DPN: 00000; GND Vias: 8 GND VIAS; Lead Free: N/A; Lifecycle Phase: N/A; Package Height: 1 MIL; Part Number: 090730100124; Rev: N/A
P_PWR_3P3 P_PWR_3P3AUX P_PWR_12V = g_2x1: CON,HDR,1X2,M,.1X.32,S,T,U,TH; DEVICE: 090730120108; Part Number: RD013; ROOM: MICRO; TAG1: 2x1, VERT,; TAG2: HDR, 2.54mm PITCH
P_SLOT = c2x82_pcie_16x_skt: CON,EC,22X142,1MM,S,G,PRFT,PCI; DEVICE: 120229082304; Part Number: UT198; ROOM: PCIE1; SUB: SUB*_KHPPX; TAG1: PCI-E 16X CONNECTOR; TAG2: PCI-E SPECIFICATION 1.0a; TAG3: PRESS-FIT SOCKET
SHUNT1-SHUNT12 = add_part: Part Number: CNDCM
C47 = cap: CAP,4.7UF,10%,6.3V,X5R,0603; DEVICE: 090729120220; Part Number: K9653; ROOM: MCU; TOLERANCE: 10%; VOLTAGE: 6.3V
C48-C50 C54 C56 C123 = cap: CAP,.1UF,10%,16V,X7R,0402; ALT_SYMBOLS: (SMX0402B); DEVICE: 090729120334; Part Number: P8155; ROOM: MCU; TOLERANCE: 10%; VOLTAGE: 16V
C51 C52 C135 = cap: CAP,10UF,10%,6.3V,X6S,0805; DEVICE: 090729120217; Part Number: K8610; ROOM: MCU; TOLERANCE: 10%; VOLTAGE: 6.3V
C53 = cap: CAP,10UF,20%,16V,X6S,0603; DEVICE: 140902090012; Part Number: 3MRV8; ROOM: MCU; TOLERANCE: 20%; VOLTAGE: 16V
C55 = cap: CAP,1UF,10%,16V,X7R,0603; DEVICE: 090729120352; Part Number: RY497; ROOM: MCU; TOLERANCE: 10%; VOLTAGE: 16V
D3 D4 = g_diode_bi_tvs: DIODE,SRG SUP,24V,SM,0603; DEVICE: 091006150800; DPN: G9464; Part Number: G9464; ROOM: MCU; TAG1: SRG SUP; TAG2: 24V, 0603
DS_3P3AUX1 DS_3P3AUX2 DS_3P3AUX4-DS_3P3AUX7 = g_led_a1_c2: LED,0603,CLR,GRN,2.5V,2MA,SMD; CLASS: DISCRETE; DPN: P0HK6; LED Color: GRN; Lead Free: Yes; Lifecycle Phase: X Revision; Manufacturer: KINGBRIGHT CORPORATION; Package Height: 0.95 MM; Package Size: 0603; Package Type: SMD; Part Number: P0HK6; Rev: X00-00; Voltage: 2.5V
L2 L32 = g_ind: FE,BEAD,300MA,0402,220OHMS; DEVICE: 111007074704; Part Number: MRKNK; ROOM: MCU; Rated Current: 300m
P1 = g_2x5_oe: CON,HDR,2X5,M,1.27MM,G,SM; DEVICE: 090730120355; Part Number: XP037; ROOM: MCU; TAG2: PLUG, 1.27mm PITCH
P5-P7 P_FANON1 P_TCRIT1 P_TWARN1 = g_2x1: CON,HDR,1X2,M,.1X.32,S,T,U,TH; CLASS: IO; DPN: RD013; Lead Free: Yes; Lifecycle Phase: A Revision; Manufacturer: FCI; Manufacturer PN: 78511-402HLF; Package Height: 426 MIL; Package Size: HDR1X2; Package Type: TH; Part Number: RD013; Pin Info: 2.54MM PITCH; ROOM: MCU; Rev: A00-00; SUB: NP
P8 = g_1x8: CON,HDR,1X8,M,.1X.23,S,T,U,TH; Manufacturer: FCI; Manufacturer PN: 78511-408HLF; Package Height: 426 MIL; Part Number: HX0CD; SUB: NP
P_M2_I2C_MASTER = g_1x4: CON,HDR,1X4,M,2.54MM,S,T,U,TH; Manufacturer: FCI; Manufacturer PN: 78511-404HLF; Package Height: 426 MIL; Package Size: HDR1X4; Package Type: TH; Part Number: Y9609; ROOM: MCU
P_UART1 = g_1x4: CON,HDR,1X4,M,2.54MM,S,T,U,TH; CLASS: IO; DPN: F3X1F; Lead Free: Yes; Lifecycle Phase: A Revision; Manufacturer: FOXCONN; Manufacturer PN: HB1104E; Package Height: 332 MIL; Package Size: HDR1X4; Package Type: TH; Part Number: F3X1F; Pin Info: 2.54MM PITCH; ROOM: MCU; Rev: A00-00; SUB: NP
P_USB = c_ara1: CON,USB,24P,F,RH,F,TH,TYPEC; CLASS: IO; DPN: N30MT; Lead Free: Yes; Lifecycle Phase: Preliminary; Manufacturer: CNC; Manufacturer PN: C-ARA1-AK512; Package Height: 5.94 MM; Package Type: SMD/TH; Part Number: N30MT; ROOM: MCU; Rev: Introductory
R43-R47 = res: RES,4.7K,1/16W,5%,THKFLM,0402; DEVICE: 090729121131; Part Number: N5300; ROOM: MCU; Rated Power: 62.5mW; TOLERANCE: 5%
R48 R50 = res: RES,10K,1/16W,1%,THKFLM,0402; DEVICE: 090729121122; Part Number: N1256; ROOM: MCU; Rated Power: 62.5mW; TOLERANCE: 1%
R49 = res: RES,10K,1/16W,1%,THKFLM,0402; DEVICE: 090729121122; Part Number: N1256; ROOM: MCU; Rated Power: 62.5mW; SUB: NP; TOLERANCE: 1%
R51 = res: RES,330,1/16W,5%,THKFLM,0402; DEVICE: 090729120636; Part Number: D7162; ROOM: MCU; Rated Power: 62.5mW; TOLERANCE: 5%
R52 = res: RES,4.7K,1/16W,5%,THKFLM,0402; DEVICE: 090729121131; Part Number: N5300; ROOM: MCU; Rated Power: 62.5mW; SUB: <SUB>; TOLERANCE: 5%
R53 = res: RES,4.7K,1/16W,5%,THKFLM,0402; DEVICE: 090729121131; Part Number: N5300; ROOM: MCU; Rated Power: 62.5mW; SUB: NP; TOLERANCE: 5%
R93 R94 = res: RES,5.1K,1/16W,1%,THKFLM,0402; CLASS: DISCRETE; DPN: X9651; Lead Free: Yes; Lifecycle Phase: A Revision; Manufacturer: SEI ELECTRONICS INC; Manufacturer PN: RMCF 1/16S 5101 1%; Material: Thick Film; Package Height: 16 MIL; Package Size: 0402; Package Type: SMD; Part Number: X9651; ROOM: MCU; Rated Power: 62.5mW; Rev: A00-00; Tolerance: 1%
R95 R96 R937 R938 = res: RES,0,1/16W,5%,THKFLM,0402; ALT_SYMBOLS: (SMX0402B); CLASS: DISCRETE; DPN: YY941; Lead Free: Yes; Lifecycle Phase: A Revision; Manufacturer: KOA; Manufacturer PN: RK73Z1ETTP; Material: Thick Film; Package Height: 0.5334 MM; Package Size: 0201; Package Type: SMD; Part Number: N5219; ROOM: MCU; Rated Power: 62.5mW; Rev: A00-00; SUB: NP; Tolerance: 5%
R102 R103 R935 R936 R939-R942 = res: RES,0,1/16W,5%,THKFLM,0402; ALT_SYMBOLS: (SMX0402B); CLASS: DISCRETE; DPN: YY941; Lead Free: Yes; Lifecycle Phase: A Revision; Manufacturer: KOA; Manufacturer PN: RK73Z1ETTP; Material: Thick Film; Package Height: 0.5334 MM; Package Size: 0201; Package Type: SMD; Part Number: N5219; ROOM: MCU; Rated Power: 62.5mW; Rev: A00-00; Tolerance: 5%
R385 R386 = res: RES,1K,1/16W,5%,THKFLM,0402; DEVICE: 090729120908; Part Number: J5741; ROOM: MCU; Rated Power: 62.5mW; SUB: NP; TOLERANCE: 5%
R387 = res: RES,1K,1/16W,5%,THKFLM,0402; DEVICE: 090729120908; Part Number: J5741; ROOM: MCU; Rated Power: 62.5mW; TOLERANCE: 5%
R388-R390 = res: RES,0,1/16W,5%,THKFLM,0402; CLASS: DISCRETE; DEVICE: 090729121124; DPN: N5219; Lead Free: Yes; Lifecycle Phase: A Revision; Manufacturer: KOA; Manufacturer PN: RK73Z1ETTP; Material: Thick Film; Package Height: 16 MIL; Package Size: 0402; Package Type: SMD; Part Number: N5219; ROOM: MCU; Rated Power: 62.5mW; Rev: A00-00; TOLERANCE: 5%
R97 R900 R946-R949 = res: RES,324,1/16W,1%,THKFLM,0402; CLASS: DISCRETE; DPN: D9921; Lead Free: Yes; Lifecycle Phase: A Revision; Manufacturer: KOA; Manufacturer PN: RK73H1ETTP3240F; Package Height: 16 MIL; Package Size: 0402; Package Type: SMD; Part Number: D9921; Rated Power: 62.5mW; Rev: A00-00; Tolerance: 1%
SW1 = sw_tl1015af160qg: SWT, PB, SPST, MOM, 50MA, 12V, SMT; DEVICE: 090730100106; Part Number: HH058; ROOM: MCU; TAG1: TL1015AF160QG
U7 = atsamd21j18a_mu: IC,SAMD21J18A,QFN64,MCU; Manufacturer: MICROCHIP TECHNOLOGY INC.; Package Height: 1 MM; Part Number: X29MY
U37 = pca9548apw_16: IC,PCA9546A,TSSOP16,BUS-SWT; CLASS: IC; DPN: 4FWH6; Lead Free: Yes; Lifecycle Phase: X Revision; Manufacturer: NXP SEMICONDUCTOR; Manufacturer PN: PCA9546APW; Package Height: 1.1 MM; Package Size: TSSOP16; Package Type: SMD; Part Number: 4FWH6; ROOM: MCU; Rev: X00-00
J_OCP1 J_OCP2 = c84edg_amp: CON,EC,168,.6MM,S,G,ST; CLASS: IO; DPN: 7HYMF; Lead Free: Yes; Lifecycle Phase: X Revision; Manufacturer: AMPHENOL; Manufacturer PN: ME1016813401311; Package Height: 6 MM; Package Type: SMD; Part Number: 7HYMF; ROOM: OCPCONN; Rev: X00-00
P_PERST_OCP1 P_PERST_OCP2 = g_2x3_oe: CON,HDR,2X3,M,.1X.32,S,T,U,TH; Manufacturer: FCI; Package Height: 411.42 MIL; Part Number: 21597
R54 R55 R59 R99 R897 = res: RES,4.7K,1/16W,5%,THKFLM,0402; DEVICE: 090729121131; Part Number: N5300; Rated Power: 62.5mW; SUB: NP; TOLERANCE: 5%
R56 R58 R60 R61 R898 = res: RES,0,1/20W,5%,THKFLM,0201; ALT_SYMBOLS: (R0201_R4,R0201M_FOX); CLASS: DISCRETE; DPN: YY941; Lead Free: Yes; Lifecycle Phase: A Revision; Manufacturer: KOA; Manufacturer PN: RK73Z1HTQTC; Material: Thick Film; Package Height: 0.33 MM; Package Size: 0201; Package Type: SMD; Part Number: YY941; ROOM: OCPCONN; Rated Power: 50mW; Rev: A00-00; Tolerance: 5%
R57 R100 R899 = res: RES,0,1/16W,1%,THKFLM,0402; CLASS: DISCRETE; DEVICE: 090729121131; DPN: 9K341; Lead Free: Yes; Lifecycle Phase: A Revision; Manufacturer: SEI ELECTRONICS INC; Manufacturer PN: RMCF 1/16S 0 1%; Material: Thick Film; Package Height: 16 MIL; Package Size: 0402; Package Type: SMD; Part Number: 9K341; Rated Power: 62.5mW; Rev: A00-00; TOLERANCE: 1%
R62-R65 R101 = res: RES,4.7K,1/16W,5%,THKFLM,0402; DEVICE: 090729121131; Part Number: N5300; Rated Power: 62.5mW; TOLERANCE: 5%
R112 R113 = res: RES,4.7K,1/16W,5%,THKFLM,0402; CLASS: DISCRETE; DEVICE: 090729121131; DPN: N5300; Lead Free: Yes; Lifecycle Phase: A Revision; Manufacturer: KOA; Manufacturer PN: RK73B1ETTP472J; Material: Thick Film; Package Height: 16 MIL; Package Size: 0402; Package Type: SMD; Part Number: N5300; Rated Power: 62.5mW; Rev: A00-00; TOLERANCE: 5%
R129-R131 = res: RES,0,1/20W,5%,THKFLM,0201; ALT_SYMBOLS: (R0201_R4,R0201M_FOX); CLASS: DISCRETE; DPN: YY941; Lead Free: Yes; Lifecycle Phase: A Revision; Manufacturer: KOA; Manufacturer PN: RK73Z1HTQTC; Material: Thick Film; Package Height: 0.33 MM; Package Size: 0201; Package Type: SMD; Part Number: YY941; ROOM: OCPCONN1; Rated Power: 50mW; Rev: A00-00; Tolerance: 5%
R132-R137 = res: RES,4.7K,1/16W,5%,THKFLM,0402; DEVICE: 090729121131; Part Number: N5300; ROOM: OCPCONN1; Rated Power: 62.5mW; TOLERANCE: 5%
R895 = res: RES,4.7K,1/16W,5%,THKFLM,0402; DEVICE: 090729121131; Part Number: N5300; Rated Power: 62.5mW; SUB: <SUB>; TOLERANCE: 5%
R896 = res: RES,0,1/16W,1%,THKFLM,0402; CLASS: DISCRETE; DEVICE: 090729121131; DPN: 9K341; Lead Free: Yes; Lifecycle Phase: A Revision; Manufacturer: SEI ELECTRONICS INC; Manufacturer PN: RMCF 1/16S 0 1%; Material: Thick Film; Package Height: 16 MIL; Package Size: 0402; Package Type: SMD; Part Number: 9K341; Rated Power: 62.5mW; Rev: A00-00; SUB: NP; TOLERANCE: 1%
C130 C141 = cap: CAP,1UF,10%,16V,X7R,0603; DEVICE: 090729120352; Part Number: RY497; TOLERANCE: 10%; VOLTAGE: 16V
C140 = cap: CAP,10UF,20%,6.3V,X5R,0603; DEVICE: 090729120437; Part Number: YT654; ROOM: CKBUF; TOLERANCE: 20%; VOLTAGE: 6.3V
J_MXIO0 = G03V21322HR: CON,PCIE,160S+4P,F,V,G,SM,MCIO; DPN: YHYWJ; Manufacturer: AMPHENOL; Package Height: 9.65 MM; Package Type: SMD/TH; Part Number: YHYWJ; ROOM: PE_MT_R5
L34 = g_ind: FE,BEAD,200MA,0603,600OHM@100M; DEVICE: 090729180941; Part Number: JW704; Rated Current: 200m
R968 R970 R971 = res: RES,1K,1/32W,5%,THKFLM,0402; DEVICE: 091106110100; Part Number: 92260; Rated Power: 31.25mW; SUB: NP; TOLERANCE: 5%
R969 R990 = res: RES,1K,1/32W,5%,THKFLM,0402; DEVICE: 091106110100; Part Number: 92260; Rated Power: 31.25mW; TOLERANCE: 5%
R978 R979 = res: RES,42.2,1/16W,1%,THKFLM,0402; DEVICE: 090729121124; Manufacturer: CYNTEC; Manufacturer PN: PFR05S42R2F; Package Height: 0.5334 MM; Part Number: G861N; ROOM: CKBUF; Rated Power: 62.5mW; TOLERANCE: 1%
R980 R981 = res: RES,88.7,1/16W,1%,THKFLM,0402; DEVICE: 091106110100; Manufacturer: SEI ELECTRONICS INC; Manufacturer PN: RMCF 1/16S 88.7 1%; Package Height: 0.5334 MM; Part Number: 98FVG; Rated Power: 62.5mW; TOLERANCE: 1%
U79 = SI53307-B-GM: IC,SI53307-B,QFN16,2OUT,CLKBUF; Manufacturer: SILICON LABORATORIES; Package Height: 0.9 MM; Part Number: GYG4F

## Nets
GND: C1.1 C2.1 C3.1 C4.1 C5.1 C6.1 C47.1 C48.1 C49.1 C50.1 C51.2 C52.2 C53.1 C54.1 C55.1 C56.2 C123.1 C130.2 C135.2 C140.1 C141.2 D3.2(1) D4.2(1) DS_3P3AUX1.2(C) DS_3P3AUX2.2(C) DS_3P3AUX4.2(C) DS_3P3AUX5.2(C) DS_3P3AUX6.2(C) DS_3P3AUX7.2(C) J_MXIO0.A1(GND_U) J_MXIO0.A4(GND_U) J_MXIO0.A7(GND_U) J_MXIO0.A10(GND_U) J_MXIO0.A13(GND_U) J_MXIO0.A16(GND_U) J_MXIO0.A19(GND_U) J_MXIO0.A22(GND_U) J_MXIO0.A25(GND_U) J_MXIO0.A28(GND_U) J_MXIO0.A31(GND_U) J_MXIO0.A34(GND_U) J_MXIO0.A37(GND_U) J_MXIO0.A38(GND_L_A1) J_MXIO0.A41(GND_L_A4) J_MXIO0.A44(GND_L_A7) J_MXIO0.A47(GND_L_A10) J_MXIO0.A50(GND_L_A13) J_MXIO0.A53(GND_L_A16) J_MXIO0.A56(GND_L_A19) J_MXIO0.A59(GND_L_A22) J_MXIO0.A62(GND_L_A25) J_MXIO0.A65(GND_L_A28) J_MXIO0.A68(GND_L_A31) J_MXIO0.A71(GND_L_A34) J_MXIO0.A74(GND_L_A37) J_MXIO0.B1(GND_U) J_MXIO0.B4(GND_U) J_MXIO0.B7(GND_U) J_MXIO0.B10(GND_U) J_MXIO0.B13(GND_U) J_MXIO0.B16(GND_U) J_MXIO0.B19(GND_U) J_MXIO0.B22(GND_U) J_MXIO0.B25(GND_U) J_MXIO0.B28(GND_U) J_MXIO0.B31(GND_U) J_MXIO0.B34(GND_U) J_MXIO0.B37(GND_U) J_MXIO0.B38(GND_L_B1) J_MXIO0.B41(GND_L_B4) J_MXIO0.B44(GND_L_B7) J_MXIO0.B47(GND_L_B10) J_MXIO0.B50(GND_L_B13) J_MXIO0.B53(GND_L_B16) J_MXIO0.B56(GND_L_B19) J_MXIO0.B59(GND_L_B22) J_MXIO0.B62(GND_L_B25) J_MXIO0.B65(GND_L_B28) J_MXIO0.B68(GND_L_B31) J_MXIO0.B71(GND_L_B34) J_MXIO0.B74(GND_L_B37) J_MXIO0.PA1(GND) J_MXIO0.PB1(GND) J_OCP1.A1 J_OCP1.A2 J_OCP1.A3 J_OCP1.A4 J_OCP1.A5 J_OCP1.A6 J_OCP1.A10 J_OCP1.A13 J_OCP1.A16 J_OCP1.A19 J_OCP1.A22 J_OCP1.A25 J_OCP1.A28 J_OCP1.A29 J_OCP1.A32 J_OCP1.A35 J_OCP1.A38 J_OCP1.A41 J_OCP1.A43 J_OCP1.A46 J_OCP1.A49 J_OCP1.A52 J_OCP1.A55 J_OCP1.A58 J_OCP1.A61 J_OCP1.A64 J_OCP1.A67 J_OCP1.B13 J_OCP1.B16 J_OCP1.B19 J_OCP1.B22 J_OCP1.B25 J_OCP1.B28 J_OCP1.B29 J_OCP1.B32 J_OCP1.B35 J_OCP1.B38 J_OCP1.B41 J_OCP1.B43 J_OCP1.B46 J_OCP1.B49 J_OCP1.B52 J_OCP1.B55 J_OCP1.B58 J_OCP1.B61 J_OCP1.B64 J_OCP1.B67 J_OCP1.OCP_A10 J_OCP1.OCP_A13 J_OCP1.OCP_B10 J_OCP1.OCP_B13 J_OCP2.A1 J_OCP2.A2 J_OCP2.A3 J_OCP2.A4 J_OCP2.A5 J_OCP2.A6 J_OCP2.A10 J_OCP2.A13 J_OCP2.A16 J_OCP2.A19 J_OCP2.A22 J_OCP2.A25 J_OCP2.A28 J_OCP2.A29 J_OCP2.A32 J_OCP2.A35 J_OCP2.A38 J_OCP2.A41 J_OCP2.A43 J_OCP2.A46 J_OCP2.A49 J_OCP2.A52 J_OCP2.A55 J_OCP2.A58 J_OCP2.A61 J_OCP2.A64 J_OCP2.A67 J_OCP2.B13 J_OCP2.B16 J_OCP2.B19 J_OCP2.B22 J_OCP2.B25 J_OCP2.B28 J_OCP2.B29 J_OCP2.B32 J_OCP2.B35 J_OCP2.B38 J_OCP2.B41 J_OCP2.B43 J_OCP2.B46 J_OCP2.B49 J_OCP2.B52 J_OCP2.B55 J_OCP2.B58 J_OCP2.B61 J_OCP2.B64 J_OCP2.B67 J_OCP2.OCP_A10 J_OCP2.OCP_A13 J_OCP2.OCP_B10 J_OCP2.OCP_B13 MH1.1 MH2.1 MH3.1 MH4.1 MH5.1 MH6.1 MH7.1 MH8.1 MH9.1 MH10.1 P1.3 P1.5 P5.2 P6.2 P7.2 P8.2 P8.8 P_M2_I2C_MASTER.4 P_SLOT.A1(PRSNT1_N) P_SLOT.A4(GND) P_SLOT.A12(GND) P_SLOT.A15(GND) P_SLOT.A18(GND) P_SLOT.A20(GND) P_SLOT.A23(GND) P_SLOT.A24(GND) P_SLOT.A27(GND) P_SLOT.A28(GND) P_SLOT.A31(GND) P_SLOT.A34(GND) P_SLOT.A37(GND) P_SLOT.A38(GND) P_SLOT.A41(GND) P_SLOT.A42(GND) P_SLOT.A45(GND) P_SLOT.A46(GND) P_SLOT.A49(GND) P_SLOT.A51(GND) P_SLOT.A55(GND) P_SLOT.A58(GND) P_SLOT.A59(GND) P_SLOT.A62(GND) P_SLOT.A63(GND) P_SLOT.A66(GND) P_SLOT.A67(GND) P_SLOT.A70(GND) P_SLOT.A71(GND) P_SLOT.A74(GND) P_SLOT.A75(GND) P_SLOT.A78(GND) P_SLOT.A79(GND) P_SLOT.A82(GND) P_SLOT.B4(GND) P_SLOT.B7(GND) P_SLOT.B13(GND) P_SLOT.B16(GND) P_SLOT.B18(GND) P_SLOT.B21(GND) P_SLOT.B22(GND) P_SLOT.B25(GND) P_SLOT.B26(GND) P_SLOT.B29(GND) P_SLOT.B32(GND) P_SLOT.B35(GND) P_SLOT.B36(GND) P_SLOT.B39(GND) P_SLOT.B40(GND) P_SLOT.B43(GND) P_SLOT.B44(GND) P_SLOT.B47(GND) P_SLOT.B49(GND) P_SLOT.B52(GND) P_SLOT.B53(GND) P_SLOT.B56(GND) P_SLOT.B57(GND) P_SLOT.B60(GND) P_SLOT.B61(GND) P_SLOT.B64(GND) P_SLOT.B65(GND) P_SLOT.B68(GND) P_SLOT.B69(GND) P_SLOT.B72(GND) P_SLOT.B73(GND) P_SLOT.B76(GND) P_SLOT.B77(GND) P_SLOT.B80(GND) P_UART1.4 P_USB.A1 P_USB.A12 P_USB.B1 P_USB.B12 P_USB.MH1 P_USB.MH2 P_USB.MH3 P_USB.MH4 P_USB.MH5 P_USB.MH6 P_USB.MH7 P_USB.MH8 R43.1 R44.1 R45.1 R52.1 R53.1 R57.1 R58.1 R60.1 R61.1 R93.2 R94.1 R100.1 R112.1 R113.1 R129.1 R130.1 R131.1 R896.1 R899.1 R939.2 R940.2 R941.2 R942.2 R970.1 R971.1 R980.1 R981.1 SW1.2(B1) U7.7(GNDANA) U7.22(GND_1) U7.33(GND_2) U7.47(GND_3) U7.54(GND_4) U7.65(EPAD) U37.1(A0) U37.2(A1) U37.8(VSS) U37.13(A2) U79.4(GND1) U79.15(GND2) U79.17(GND_PAD) ; also on sheet 10 11 12 13 14 15 16
VDDANA: C53.2 C54.2 L2.2 U7.8(VDDANA)
ATX_PWR_OK: U7.16(PA07) ; also on sheet 13
AUX_EN: J_OCP1.B12 R59.1 R112.2 U7.18(PA09) ; also on sheet 10 13
AUX_EN_OCP2: J_OCP2.B12 R132.1 U7.9(PB06) ; also on sheet 10 13
BIF0_N: J_OCP1.B7 R58.2
BIF1_N: J_OCP1.B8 R60.2
BIF2_N: J_OCP1.B9 R61.2
BRD_VER_0: R49.1 R52.2 U7.42(PA21)
BRD_VER_1: R50.1 R53.2 U7.32(PA15)
CK_100M_PE_HOST1_DN: R979.1 R980.2 ; also on sheet 13
CK_100M_PE_HOST1_DP: R978.1 R981.2 ; also on sheet 13
CK_OCP_A_100M_PE_DN: J_MXIO0.A49(REFCLKn_A_L_A12) U79.7(CLK0b)
CK_OCP_A_100M_PE_DP: J_MXIO0.A48(REFCLKp_A_L_A11) U79.6(CLK0)
CK_OCP_B_100M_PE_DN: J_MXIO0.A12(REFCLKn_B_U) U79.3(CLK1b)
CK_OCP_B_100M_PE_DP: J_MXIO0.A11(REFCLKp_B_U) U79.2(CLK1)
CLK_100M_OCP0_DN: J_OCP1.B14 ; also on sheet 13
CLK_100M_OCP0_DP: J_OCP1.B15 ; also on sheet 13
CLK_100M_OCP1_DN: J_OCP1.A14 ; also on sheet 13
CLK_100M_OCP1_DP: J_OCP1.A15 ; also on sheet 13
CLK_100M_OCP2_DN: J_OCP1.OCP_B11 ; also on sheet 13
CLK_100M_OCP2_DP: J_OCP1.OCP_B12 ; also on sheet 13
CLK_100M_OCP3_DN: J_OCP1.OCP_A11 ; also on sheet 13
CLK_100M_OCP3_DP: J_OCP1.OCP_A12 ; also on sheet 13
CLK_100M_OCP4_DN: J_OCP2.B14 ; also on sheet 14
CLK_100M_OCP4_DP: J_OCP2.B15 ; also on sheet 14
CLK_100M_OCP5_DN: J_OCP2.A14 ; also on sheet 14
CLK_100M_OCP5_DP: J_OCP2.A15 ; also on sheet 14
CLK_100M_OCP6_DN: J_OCP2.OCP_B11 ; also on sheet 14
CLK_100M_OCP6_DP: J_OCP2.OCP_B12 ; also on sheet 14
CLK_100M_OCP7_DN: J_OCP2.OCP_A11 ; also on sheet 14
CLK_100M_OCP7_DP: J_OCP2.OCP_A12 ; also on sheet 14
CLK_NCSI: J_OCP1.OCP_A14 ; also on sheet 11
CLK_NCSI_OCP2: J_OCP2.OCP_A14 ; also on sheet 12
HEARTBEAT: R948.2 U7.60(PB31)
HOST1_AB_CLK_SEL: U7.26(PB13) U79.14(CLK_SEL)
HOST2_AB_CLK_SEL: U7.27(PB14) ; also on sheet 16
HOST2_SMB_CLK: R937.2 ; also on sheet 16
HOST2_SMB_SDA: R938.2 ; also on sheet 16
HOST_SMB_CLK: J_MXIO0.B45(SMSCL_A_L_B8) R95.2
HOST_SMB_SDA: J_MXIO0.B46(SMSDA_A_L_B9) R96.2
MAIN_EN: J_OCP1.OCP_B2 R54.1 R113.2 U7.44(PA23)
MAIN_EN_OCP2: J_OCP2.OCP_B2 U7.50(PB23)
MCU_CLK: P_M2_I2C_MASTER.3 R47.1 R386.1 R389.1 U7.36(PA17)
MCU_RESET_N: P1.10 P_M2_I2C_MASTER.1 R48.1 R51.1 R390.1 SW1.1(A1) U7.52(RESET_N)
MCU_SDA: P_M2_I2C_MASTER.2 R46.1 R385.1 R388.1 U7.35(PA16)
NC_B68: J_OCP1.B68
NC_B68_OCP2: J_OCP2.B68
NC_B69: J_OCP1.B69
NC_B69_OCP2: J_OCP2.B69
NC_SEC_SMB_RST_OCP2_N: J_OCP2.A9
NC_SMB_RST_N: J_OCP1.A9
NC_WAKE_OCP2_N: J_OCP2.OCP_A3
NCSI_RST_N: U7.53(PA28) ; also on sheet 11
NCSI_RST_OCP2_N: U7.51(PA27) ; also on sheet 12
NIC_PWR_GOOD_OCP1: J_OCP1.OCP_B1 R97.2 U7.61(PB00) ; also on sheet 10
NIC_PWR_GOOD_OCP2: J_OCP2.OCP_B1 R900.2 U7.62(PB01) ; also on sheet 10
NTP_R5_SL11_3P3AUX_MGMT: J_MXIO0.A45(3p3AUX_MGMT_L_A8)
OCP2_CLK_SEL: U7.25(PB12) ; also on sheet 14
OCP_NCSI_CRS_DV: J_OCP1.OCP_B14 ; also on sheet 10
OCP_NCSI_CRS_DV_OCP2: J_OCP2.OCP_B14 ; also on sheet 10
OCP_NCSI_RXD0: J_OCP1.OCP_B9 ; also on sheet 10
OCP_NCSI_RXD0_OCP2: J_OCP2.OCP_B9 ; also on sheet 10
OCP_NCSI_RXD1: J_OCP1.OCP_B8 ; also on sheet 10
OCP_NCSI_RXD1_OCP2: J_OCP2.OCP_B8 ; also on sheet 10
OCP_NCSI_TXD0: J_OCP1.OCP_A9 ; also on sheet 10
OCP_NCSI_TXD0_OCP2: J_OCP2.OCP_A9 ; also on sheet 10
OCP_NCSI_TXD1: J_OCP1.OCP_A8 ; also on sheet 10
OCP_NCSI_TXD1_OCP2: J_OCP2.OCP_A8 ; also on sheet 10
OCP_NCSI_TXEN: J_OCP1.OCP_A7 ; also on sheet 10
OCP_NCSI_TXEN_OCP2: J_OCP2.OCP_A7 ; also on sheet 10
PE_CPU_OCP_0_DN: J_MXIO0.B73(PETn0_L_B36) J_OCP1.B17
PE_CPU_OCP_0_DP: J_MXIO0.B72(PETp0_L_B35) J_OCP1.B18
PE_CPU_OCP_1_DN: J_MXIO0.B70(PETn1_L_B33) J_OCP1.B20
PE_CPU_OCP_1_DP: J_MXIO0.B69(PETp1_L_B32) J_OCP1.B21
PE_CPU_OCP_2_DN: J_MXIO0.B61(PETn2_L_B24) J_OCP1.B23
PE_CPU_OCP_2_DP: J_MXIO0.B60(PETp2_L_B23) J_OCP1.B24
PE_CPU_OCP_3_DN: J_MXIO0.B58(PETn3_L_B21) J_OCP1.B26
PE_CPU_OCP_3_DP: J_MXIO0.B57(PETp3_L_B20) J_OCP1.B27
PE_CPU_OCP_4_DN: J_MXIO0.B55(PETn4_L_B18) J_OCP1.B30
PE_CPU_OCP_4_DP: J_MXIO0.B54(PETp4_L_B17) J_OCP1.B31
PE_CPU_OCP_5_DN: J_MXIO0.B52(PETn5_L_B15) J_OCP1.B33
PE_CPU_OCP_5_DP: J_MXIO0.B51(PETp5_L_B14) J_OCP1.B34
PE_CPU_OCP_6_DN: J_MXIO0.B43(PETn6_L_B6) J_OCP1.B36
PE_CPU_OCP_6_DP: J_MXIO0.B42(PETp6_L_B5) J_OCP1.B37
PE_CPU_OCP_7_DN: J_MXIO0.B40(PETn7_L_B3) J_OCP1.B39
PE_CPU_OCP_7_DP: J_MXIO0.B39(PETp7_L_B2) J_OCP1.B40
PE_CPU_OCP_8_DN: J_MXIO0.B36(PETn8_U) J_OCP1.B44
PE_CPU_OCP_8_DP: J_MXIO0.B35(PETp8_U) J_OCP1.B45
PE_CPU_OCP_9_DN: J_MXIO0.B33(PETn9_U) J_OCP1.B47
PE_CPU_OCP_9_DP: J_MXIO0.B32(PETp9_U) J_OCP1.B48
PE_CPU_OCP_10_DN: J_MXIO0.B24(PETn10_U) J_OCP1.B50
PE_CPU_OCP_10_DP: J_MXIO0.B23(PETp10_U) J_OCP1.B51
PE_CPU_OCP_11_DN: J_MXIO0.B21(PETn11_U) J_OCP1.B53
PE_CPU_OCP_11_DP: J_MXIO0.B20(PETp11_U) J_OCP1.B54
PE_CPU_OCP_12_DN: J_MXIO0.B18(PETn12_U) J_OCP1.B56
PE_CPU_OCP_12_DP: J_MXIO0.B17(PETp12_U) J_OCP1.B57
PE_CPU_OCP_13_DN: J_MXIO0.B15(PETn13_U) J_OCP1.B59
PE_CPU_OCP_13_DP: J_MXIO0.B14(PETp13_U) J_OCP1.B60
PE_CPU_OCP_14_DN: J_MXIO0.B6(PETn14_U) J_OCP1.B62
PE_CPU_OCP_14_DP: J_MXIO0.B5(PETp14_U) J_OCP1.B63
PE_CPU_OCP_15_DN: J_MXIO0.B3(PETn15_U) J_OCP1.B65
PE_CPU_OCP_15_DP: J_MXIO0.B2(PETp15_U) J_OCP1.B66
PE_CPU_OCP_16_DN: J_OCP2.B17 ; also on sheet 16
PE_CPU_OCP_16_DP: J_OCP2.B18 ; also on sheet 16
PE_CPU_OCP_17_DN: J_OCP2.B20 ; also on sheet 16
PE_CPU_OCP_17_DP: J_OCP2.B21 ; also on sheet 16
PE_CPU_OCP_18_DN: J_OCP2.B23 ; also on sheet 16
PE_CPU_OCP_18_DP: J_OCP2.B24 ; also on sheet 16
PE_CPU_OCP_19_DN: J_OCP2.B26 ; also on sheet 16
PE_CPU_OCP_19_DP: J_OCP2.B27 ; also on sheet 16
PE_CPU_OCP_20_DN: J_OCP2.B30 ; also on sheet 16
PE_CPU_OCP_20_DP: J_OCP2.B31 ; also on sheet 16
PE_CPU_OCP_21_DN: J_OCP2.B33 ; also on sheet 16
PE_CPU_OCP_21_DP: J_OCP2.B34 ; also on sheet 16
PE_CPU_OCP_22_DN: J_OCP2.B36 ; also on sheet 16
PE_CPU_OCP_22_DP: J_OCP2.B37 ; also on sheet 16
PE_CPU_OCP_23_DN: J_OCP2.B39 ; also on sheet 16
PE_CPU_OCP_23_DP: J_OCP2.B40 ; also on sheet 16
PE_CPU_OCP_24_DN: J_OCP2.B44 ; also on sheet 16
PE_CPU_OCP_24_DP: J_OCP2.B45 ; also on sheet 16
PE_CPU_OCP_25_DN: J_OCP2.B47 ; also on sheet 16
PE_CPU_OCP_25_DP: J_OCP2.B48 ; also on sheet 16
PE_CPU_OCP_26_DN: J_OCP2.B50 ; also on sheet 16
PE_CPU_OCP_26_DP: J_OCP2.B51 ; also on sheet 16
PE_CPU_OCP_27_DN: J_OCP2.B53 ; also on sheet 16
PE_CPU_OCP_27_DP: J_OCP2.B54 ; also on sheet 16
PE_CPU_OCP_28_DN: J_OCP2.B56 ; also on sheet 16
PE_CPU_OCP_28_DP: J_OCP2.B57 ; also on sheet 16
PE_CPU_OCP_29_DN: J_OCP2.B59 ; also on sheet 16
PE_CPU_OCP_29_DP: J_OCP2.B60 ; also on sheet 16
PE_CPU_OCP_30_DN: J_OCP2.B62 ; also on sheet 16
PE_CPU_OCP_30_DP: J_OCP2.B63 ; also on sheet 16
PE_CPU_OCP_31_DN: J_OCP2.B65 ; also on sheet 16
PE_CPU_OCP_31_DP: J_OCP2.B66 ; also on sheet 16
PE_OCP_CPU_0_DN: J_MXIO0.A73(PERn0_L_A36) J_OCP1.A17
PE_OCP_CPU_0_DP: J_MXIO0.A72(PERp0_L_A35) J_OCP1.A18
PE_OCP_CPU_1_DN: J_MXIO0.A70(PERn1_L_A33) J_OCP1.A20
PE_OCP_CPU_1_DP: J_MXIO0.A69(PERp1_L_A32) J_OCP1.A21
PE_OCP_CPU_2_DN: J_MXIO0.A61(PERn2_L_A24) J_OCP1.A23
PE_OCP_CPU_2_DP: J_MXIO0.A60(PERp2_L_A23) J_OCP1.A24
PE_OCP_CPU_3_DN: J_MXIO0.A58(PERn3_L_A21) J_OCP1.A26
PE_OCP_CPU_3_DP: J_MXIO0.A57(PERp3_L_A20) J_OCP1.A27
PE_OCP_CPU_4_DN: J_MXIO0.A55(PERn4_L_A18) J_OCP1.A30
PE_OCP_CPU_4_DP: J_MXIO0.A54(PERp4_L_A17) J_OCP1.A31
PE_OCP_CPU_5_DN: J_MXIO0.A52(PERn5_L_A15) J_OCP1.A33
PE_OCP_CPU_5_DP: J_MXIO0.A51(PERp5_L_A14) J_OCP1.A34
PE_OCP_CPU_6_DN: J_MXIO0.A43(PERn6_L_A6) J_OCP1.A36
PE_OCP_CPU_6_DP: J_MXIO0.A42(PERp6_L_A5) J_OCP1.A37
PE_OCP_CPU_7_DN: J_MXIO0.A40(PERn7_L_A3) J_OCP1.A39
PE_OCP_CPU_7_DP: J_MXIO0.A39(PERp7_L_A2) J_OCP1.A40
PE_OCP_CPU_8_DN: J_MXIO0.A36(PERn8_U) J_OCP1.A44
PE_OCP_CPU_8_DP: J_MXIO0.A35(PERp8_U) J_OCP1.A45
PE_OCP_CPU_9_DN: J_MXIO0.A33(PERn9_U) J_OCP1.A47
PE_OCP_CPU_9_DP: J_MXIO0.A32(PERp9_U) J_OCP1.A48
PE_OCP_CPU_10_DN: J_MXIO0.A24(PERn10_U) J_OCP1.A50
PE_OCP_CPU_10_DP: J_MXIO0.A23(PERp10_U) J_OCP1.A51
PE_OCP_CPU_11_DN: J_MXIO0.A21(PERn11_U) J_OCP1.A53
PE_OCP_CPU_11_DP: J_MXIO0.A20(PERp11_U) J_OCP1.A54
PE_OCP_CPU_12_DN: J_MXIO0.A18(PERn12_U) J_OCP1.A56
PE_OCP_CPU_12_DP: J_MXIO0.A17(PERp12_U) J_OCP1.A57
PE_OCP_CPU_13_DN: J_MXIO0.A15(PERn13_U) J_OCP1.A59
PE_OCP_CPU_13_DP: J_MXIO0.A14(PERp13_U) J_OCP1.A60
PE_OCP_CPU_14_DN: J_MXIO0.A6(PERn14_U) J_OCP1.A62
PE_OCP_CPU_14_DP: J_MXIO0.A5(PERp14_U) J_OCP1.A63
PE_OCP_CPU_15_DN: J_MXIO0.A3(PERn15_U) J_OCP1.A65
PE_OCP_CPU_15_DP: J_MXIO0.A2(PERp15_U) J_OCP1.A66
PE_OCP_CPU_16_DN: J_OCP2.A17 ; also on sheet 16
PE_OCP_CPU_16_DP: J_OCP2.A18 ; also on sheet 16
PE_OCP_CPU_17_DN: J_OCP2.A20 ; also on sheet 16
PE_OCP_CPU_17_DP: J_OCP2.A21 ; also on sheet 16
PE_OCP_CPU_18_DN: J_OCP2.A23 ; also on sheet 16
PE_OCP_CPU_18_DP: J_OCP2.A24 ; also on sheet 16
PE_OCP_CPU_19_DN: J_OCP2.A26 ; also on sheet 16
PE_OCP_CPU_19_DP: J_OCP2.A27 ; also on sheet 16
PE_OCP_CPU_20_DN: J_OCP2.A30 ; also on sheet 16
PE_OCP_CPU_20_DP: J_OCP2.A31 ; also on sheet 16
PE_OCP_CPU_21_DN: J_OCP2.A33 ; also on sheet 16
PE_OCP_CPU_21_DP: J_OCP2.A34 ; also on sheet 16
PE_OCP_CPU_22_DN: J_OCP2.A36 ; also on sheet 16
PE_OCP_CPU_22_DP: J_OCP2.A37 ; also on sheet 16
PE_OCP_CPU_23_DN: J_OCP2.A39 ; also on sheet 16
PE_OCP_CPU_23_DP: J_OCP2.A40 ; also on sheet 16
PE_OCP_CPU_24_DN: J_OCP2.A44 ; also on sheet 16
PE_OCP_CPU_24_DP: J_OCP2.A45 ; also on sheet 16
PE_OCP_CPU_25_DN: J_OCP2.A47 ; also on sheet 16
PE_OCP_CPU_25_DP: J_OCP2.A48 ; also on sheet 16
PE_OCP_CPU_26_DN: J_OCP2.A50 ; also on sheet 16
PE_OCP_CPU_26_DP: J_OCP2.A51 ; also on sheet 16
PE_OCP_CPU_27_DN: J_OCP2.A53 ; also on sheet 16
PE_OCP_CPU_27_DP: J_OCP2.A54 ; also on sheet 16
PE_OCP_CPU_28_DN: J_OCP2.A56 ; also on sheet 16
PE_OCP_CPU_28_DP: J_OCP2.A57 ; also on sheet 16
PE_OCP_CPU_29_DN: J_OCP2.A59 ; also on sheet 16
PE_OCP_CPU_29_DP: J_OCP2.A60 ; also on sheet 16
PE_OCP_CPU_30_DN: J_OCP2.A62 ; also on sheet 16
PE_OCP_CPU_30_DP: J_OCP2.A63 ; also on sheet 16
PE_OCP_CPU_31_DN: J_OCP2.A65 ; also on sheet 16
PE_OCP_CPU_31_DP: J_OCP2.A66 ; also on sheet 16
PERST0_N: J_MXIO0.B48(PERST_A_L_B11_N) J_OCP1.B10 P_PERST_OCP1.2 P_PERST_OCP1.4 P_PERST_OCP1.6 U7.6(PB05)
PERST1_N: J_OCP1.A11 P_PERST_OCP1.3
PERST2_N: J_OCP1.OCP_A1 P_PERST_OCP1.1
PERST3_N: J_OCP1.OCP_A2 P_PERST_OCP1.5
PERST4_OCP2_N: J_OCP2.B10 P_PERST_OCP2.2 P_PERST_OCP2.4 P_PERST_OCP2.6 U7.5(PB04) ; also on sheet 16
PERST5_OCP2_N: J_OCP2.A11 P_PERST_OCP2.1
PERST6_OCP2_N: J_OCP2.OCP_A1 P_PERST_OCP2.3
PERST7_OCP2_N: J_OCP2.OCP_A2 P_PERST_OCP2.5
PESTI_R5_SL12_CBL_PRES_N: J_MXIO0.B12(PESTI_B_U_B12_N) ; also on sheet 16
PRSNTB0_N: J_OCP1.B42 R63.1 U7.37(PA18)
PRSNTB0_OCP2_N: J_OCP2.B42 R134.1 U7.12(PB09)
PRSNTB1_N: J_OCP1.A42 R64.1 U7.23(PB10)
PRSNTB1_OCP2_N: J_OCP2.A42 R135.1 U7.13(PA04)
PRSNTB2_N: J_OCP1.A12 R62.1 U7.31(PA14)
PRSNTB2_OCP2_N: J_OCP2.A12 R133.1 U7.14(PA05)
PRSNTB3_N: J_OCP1.B70 R65.1 U7.63(PB02)
PRSNTB3_OCP2_N: J_OCP2.B70 R136.1 U7.15(PA06)
PWRBRK_N: J_OCP1.A70 R101.1 U7.49(PB22)
PWRBRK_OCP2_N: J_OCP2.A70 R137.1 U7.4(PA03)
SCAN_CLK: J_OCP1.OCP_B6 U7.20(PA11)
SCAN_CLK_OCP2: J_OCP2.OCP_B6 U7.29(PA12)
SCAN_DATA_IN: J_OCP1.OCP_B4 U7.19(PA10)
SCAN_DATA_IN_OCP2: J_OCP2.OCP_B4 U7.24(PB11)
SCAN_DATA_OUT: J_OCP1.OCP_B5 U7.17(PA08)
SCAN_DATA_OUT_OCP2: J_OCP2.OCP_B5 U7.3(PA02)
SCAN_LD_N: J_OCP1.OCP_B3 U7.43(PA22)
SCAN_LD_OCP2_N: J_OCP2.OCP_B3 U7.30(PA13)
SEC_BIF0_OCP2_N: J_OCP2.B7 R131.2
SEC_BIF1_OCP2_N: J_OCP2.B8 R129.2
SEC_BIF2_OCP2_N: J_OCP2.B9 R130.2
SFOUT0_U79: R968.1 R970.2 U79.13(SFOUT0)
SFOUT1_U79: R969.1 R971.2 U79.8(SFOUT1)
SLOT_ID0: J_OCP1.OCP_B7 R55.1 R57.2
SLOT_ID0_OCP2: J_OCP2.OCP_B7 R895.1 R896.2
SLOT_ID1: J_OCP1.OCP_A6 R99.1 R100.2
SLOT_ID1_OCP2: J_OCP2.OCP_A6 R897.1 R899.2
SMB_CLK: J_OCP1.A7 R103.2
SMB_CLK_OCP2: J_OCP2.A7 R936.2
SMB_SDA: J_OCP1.A8 R102.2
SMB_SDA_OCP2: J_OCP2.A8 R935.2
SWCLK: P1.4 U7.57(PA30)
SWDIO: P1.2 U7.58(PA31)
TEMP_CRIT: P_TCRIT1.1 R44.2 R946.2 U7.2(PA01)
TEMP_WARN: P_TWARN1.1 R43.2 R947.2 U7.1(PA00)
UART_RX: P_UART1.3 U7.38(PA19)
UART_TX: P_UART1.2 U7.41(PA20)
USB_CC1: P_USB.A5 R93.1
USB_CC2: P_USB.B8 R94.2
USB_DAT_OCP2_DN: J_OCP2.A68 ; also on sheet 12
USB_DAT_OCP2_DP: J_OCP2.A69 ; also on sheet 12
USB_DATN: J_OCP1.A68 ; also on sheet 11
USB_DATP: J_OCP1.A69 ; also on sheet 11
USB_HS_DN: D4.1(2) P_USB.A7 P_USB.B7 U7.45(PA24)
USB_HS_DP: D3.1(2) P_USB.A6 P_USB.B6 U7.46(PA25)
V_3P3_MCU: C47.2 C48.2 C49.2 C50.2 C52.1 C123.2 L32.2 P1.1 P5.1 P6.1 P7.1 P8.1 P_FANON1.2 P_TCRIT1.2 P_TWARN1.2 P_UART1.1 R46.2 R47.2 R48.2 R49.2 R50.2 R385.2 R386.2 R387.2 U7.21(VDDIO) U7.34(VDDIO) U7.48(VDDIO) U7.56(VDDIN) U37.16(VDD)
V_3P3_SLOT: C3.2 C4.2 P_PWR_3P3.2 P_SLOT.A9(+3.3V_2) P_SLOT.A10(+3.3V_3) P_SLOT.B8(+3.3V_1)
V_3P3AUX: C51.1 C130.1 C135.1 J_OCP1.B11 J_OCP2.B11 L2.1 L32.1 L34.1 P_PWR_3P3.1 P_PWR_3P3AUX.1 R54.2 R55.2 R59.2 R62.2 R63.2 R64.2 R65.2 R99.2 R101.2 R132.2 R133.2 R134.2 R135.2 R136.2 R137.2 R895.2 R897.2 R968.2 R969.2 U79.1(VDD) ; also on sheet 10 11 12 13 14 15 16
V_3P3AUX_SLOT: C5.2 C6.2 P_PWR_3P3AUX.2 P_SLOT.B10(+3.3V_AUX)
V_12V: J_OCP1.B1 J_OCP1.B2 J_OCP1.B3 J_OCP1.B4 J_OCP1.B5 J_OCP1.B6 J_OCP2.B1 J_OCP2.B2 J_OCP2.B3 J_OCP2.B4 J_OCP2.B5 J_OCP2.B6 P_PWR_12V.1 ; also on sheet 13 15
V_12V_SLOT: C1.2 C2.2 P_PWR_12V.2 P_SLOT.A2(+12V_3) P_SLOT.A3(+12V_4) P_SLOT.B1(+12V_1) P_SLOT.B2(+12V_2) P_SLOT.B3(+12V_5)
WAKE_N: J_OCP1.OCP_A3 U7.64(PB03)
N16885524: J_OCP1.OCP_A4 R56.1
N16885526: J_OCP1.OCP_A5 R56.2
N16971830: DS_3P3AUX1.1(A) R97.1
N17145109: J_MXIO0.PA2(12V) J_MXIO0.PB2(12V)
N17187516: J_OCP2.OCP_A4 R898.1
N17187518: J_OCP2.OCP_A5 R898.2
N17194582: DS_3P3AUX2.1(A) R900.1
N17230499: C56.1 R51.2
N17230808: C55.2 U7.55(VDDCORE)
N17231389: R387.1 R390.2 U37.3(RESET_N)
N17231484: R102.1 U37.4(SD0)
N17231506: R103.1 U37.5(SC0)
N17231571: R388.2 U37.15(SDA)
N17231573: R935.1 U37.6(SD1)
N17231599: R389.2 U37.14(SCL)
N17231601: R936.1 U37.7(SC1)
N17231649: R939.1 U37.9(SD2)
N17231672: R940.1 U37.10(SC2)
N17231748: R941.1 U37.11(SD3)
N17231777: R942.1 U37.12(SC3)
N17238419: P_FANON1.1 R45.2 R949.2 U7.11(PB08)
N17261668: DS_3P3AUX4.1(A) R946.1
N17262331: DS_3P3AUX5.1(A) R947.1
N17263137: DS_3P3AUX7.1(A) R948.1
N17263139: DS_3P3AUX6.1(A) R949.1
N17292237: R990.1 U79.16(OE)
N17322745: R978.2 U79.12(Q0)
N17322761: R979.2 U79.11(Q0b)
N17349994: P8.7 U7.10(PB07)
N17349999: P8.6 U7.28(PB15)
N17350004: P8.5 U7.39(PB16)
N17350009: P8.4 U7.40(PB17)
N17350014: P8.3 U7.59(PB30)
N17393502: C140.2 C141.1 L34.2 R990.2 U79.5(VDDO)

Not connected (* = marked no-connect by the designer): J_MXIO0 A8(3p3AUX_MGMT_U) A9(FLEXIO0_B_U) A26(FLEXIO5_B_U) A27(FLEXIO6_B_U) A29(USB2p_B_U) A30(USB2n_B_U) A46(FLEXIO0_A_L_A9) A63(FLEXIO5_A_L_A26) A64(FLEXIO6_A_L_A27) A66(USB2p_A_L_A29) A67(USB2n_A_L_A30) B8(SMSCL_B_U) B9(SMSDA_B_U) B11(PERST_B_U_B11_N) B26(FLEXIO3_B_U) B27(FLEXIO4_B_U) B29(FLEXIO1_B_U) B30(FLEXIO2_B_U) B49(PESTI_A_L_B12_N) B63(FLEXIO3_A_L_B26) B64(FLEXIO4_A_L_B27) B66(FLEXIO1_A_L_B29) B67(FLEXIO2_A_L_B30) SA1(PWR_A)* SA2(PWR_A)* SA3(PWR_A)* SA4(PWR_A)* SA5(SCL_PWR_A)* SA6(SDA_PWR_A)* SB1(PWR_B)* SB2(PWR_B)* SB3(PWR_B)* SB4(PWR_B)* SB5(SCL_PWR_B)* SB6(SDA_PWR_B)*; LBL1 1(NC); P1 6* 7* 8* 9*; P_SLOT A5(JTAG_TCK)* A6(JTAG_TDI)* A7(JTAG_TDO)* A8(JTAG_TMS)* A11(PERST_N) A13(REFCLK+) A14(REFCLK-) A16(PERP0)* A17(PERN0)* A19(RSVD)* A21(PERP1)* A22(PERN1)* A25(PERP2)* A26(PERN2)* A29(PERP3)* A30(PERN3)* A32(RSVD)* A33(RSVD)* A35(PERP4)* A36(PERN4)* A39(PERP5)* A40(PERN5)* A43(PERP6)* A44(PERN6)* A47(PERP7)* A48(PERN7)* A50(RSVD)* A52(PERP8)* A53(PERN8)* A54(GND)* A56(PERP9)* A57(PERN9)* A60(PERP10)* A61(PERN10)* A64(PERP11)* A65(PERN11)* A68(PERP12)* A69(PERN12)* A72(PERP13)* A73(PERN13)* A76(PERP14)* A77(PERN14)* A80(PERP15)* A81(PERN15)* B5(SMCLK)* B6(SMDATA)* B9(JTAG_TRST_N)* B11(WAKE_N) B12(RSVD)* B14(PETP0)* B15(PETN0)* B17(PRSNT2_X1_N) B19(PETP1)* B20(PETN1)* B23(PETP2)* B24(PETN2)* B27(PETP3)* B28(PETN3)* B30(RSVD)* B31(PRSNT2_X4_N)* B33(PETP4)* B34(PETN4)* B37(PETP5)* B38(PETN5)* B41(PETP6)* B42(PETN6)* B45(PETP7)* B46(PETN7)* B48(PRSNT2_X8_N)* B50(PETP8)* B51(PETN8)* B54(PETP9)* B55(PETN9)* B58(PETP10)* B59(PETN10)* B62(PETP11)* B63(PETN11)* B66(PETP12)* B67(PETN12)* B70(PETP13)* B71(PETN13)* B74(PETP14)* B75(PETN14)* B78(PETP15)* B79(PETN15)* B81(PRSNT2_X16_N) B82(RSVD)*; P_USB A2* A3* A4* A8* A9* A10* A11* B2* B3* B4* B5* B9* B10* B11*; R95 1*; R96 1*; R937 1*; R938 1*; U79 9(Q1b)* 10(Q1)*

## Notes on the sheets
sheet 1
- OCP3 Thermal Test Fixture (TTF)
- Dual Small Form Factor (DSFF)
- Table Of Contents:
  Page 1 - Block Diagram
  Page 2 - Clock Diagram
  Page 3 - Stackup
  Page 4 - PCIe Riser Connector
  Page 5 - MCU Control
  Page 6 - Primary OCP Connector
  Page 7 - Secondary OCP Connector
  Page 8 - Primary M-XIO
  Page 9 - Secondary M-XIO
  Page 10 - Power Sequencing
  Page 11 - NCSI Isolation
  Page 12 - NCSI PHY and RJ
  Page 13 - NCSI PHY and RJ45 OCP2
  Page 14 - Clock Buf, PWR Conn
  Page 15 - Secondary Clock Buffer
  Page 16 - 3V3 Regulator
- PWA: Y0TW7
  PWB: 0PPP8
  SCH: 9XNGK
sheet 3
- NOTES:
  Multi-Host not supported
  ONLY REFCLK0 Used from system for all OCP CLK Inputs
  PESTI NOT supported in this version (no PWRBRK)
  WAKE no longer supported
  ITEMS IN RED ARE STILL OPEN
sheet 4
- PCIe Riser Card Connector
- Connect jumpers to power PCIe slot
sheet 5
- PLACE AROUND PROCESSOR SECTION FOR DEBUG
- MCU
- LOW PASS POWER FILTERING
- MCU PROGRAMMING HEADER
- ECAD: add silkscreen as follows starting Pin 1:
  3.3V
  GND
  PB30
  PB17
  PB16
  PB15
  PB07
  GND
- ROOM = MCU
- USED AS TEST POINT FOR NOW
- V_3P3_MCU DECOUPLING
sheet 6
- OCP Connector
- Pinout per OCP3.0 spec 1.0
- NCSI ARB IN AND OUT SHORTED
- ROOM = OCPCONN
sheet 7
- OCP Secondary Connector
- Pinout per OCP3.0 spec 1.0
- NCSI ARB IN AND OUT SHORTED
- ROOM = OCPCONN1
sheet 8
- HOST[1:2]_AB_CLK_SEL is low by default from the MCU
- Host PCIe Conn
  SFF-TA-1033 Compliant
sheet 9
- POWER SEQUENCE
